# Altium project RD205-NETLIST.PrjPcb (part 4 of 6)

## Sheet 5.SchDoc
size 420 x 297 mm
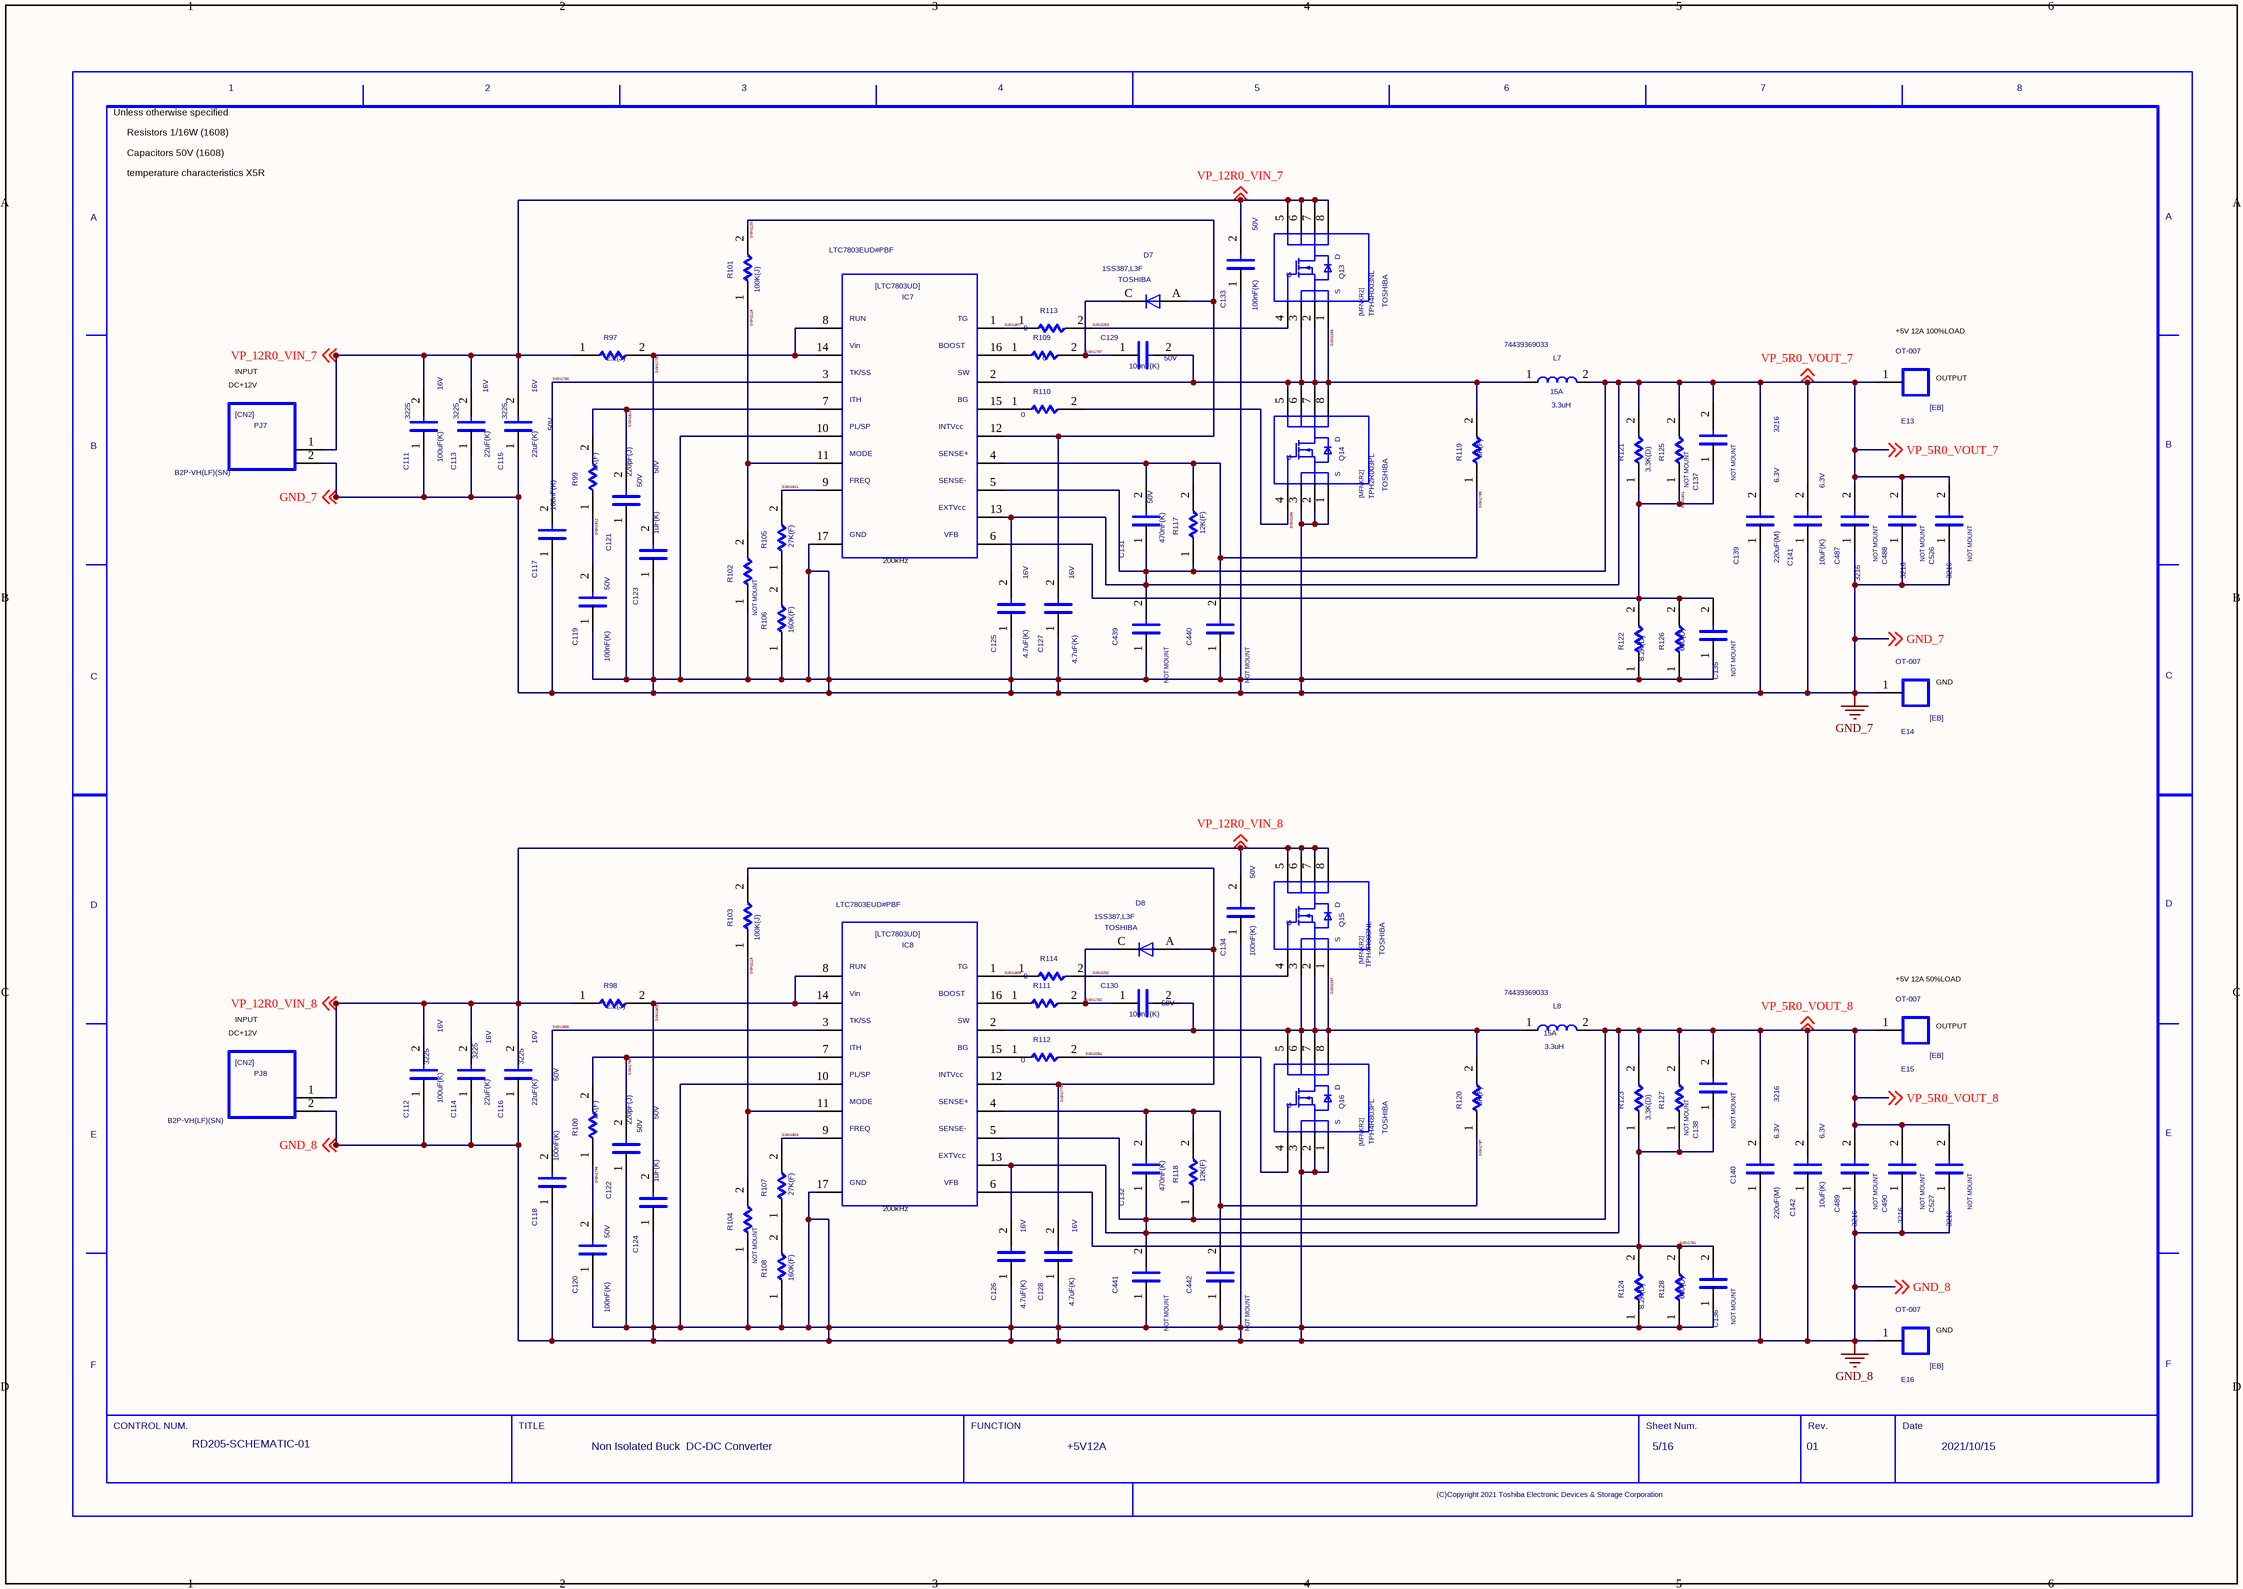
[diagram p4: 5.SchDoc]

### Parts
(Parts that share a designator on the sheet are numbered #1, #2 ... from top to bottom, then left to right.)
C111  SIZECODESMD: 3225  VAL2: 16V  VAL1: 100uF(K)  (hidden comment: C)
C112  SIZECODESMD: 3225  VAL2: 16V  VAL1: 100uF(K)  (hidden comment: C)
C113  SIZECODESMD: 3225  VAL2: 16V  VAL1: 22uF(K)  (hidden comment: C)
C114  SIZECODESMD: 3225  VAL2: 16V  VAL1: 22uF(K)  (hidden comment: C)
C115  SIZECODESMD: 3225  VAL2: 16V  VAL1: 22uF(K)  (hidden comment: C)
C116  SIZECODESMD: 3225  VAL2: 16V  VAL1: 22uF(K)  (hidden comment: C)
C117  VAL2: 50V  VAL1: 100nF(K)  (hidden comment: C)
C118  VAL2: 50V  VAL1: 100nF(K)  (hidden comment: C)
C119  VAL2: 50V  VAL1: 100nF(K)  (hidden comment: C)
C120  VAL2: 50V  VAL1: 100nF(K)  (hidden comment: C)
C121  VAL2: 50V  VAL1: 220pF(J)  (hidden comment: C)
C122  VAL2: 50V  VAL1: 220pF(J)  (hidden comment: C)
C123  VAL2: 50V  VAL1: 1uF(K)  (hidden comment: C)
C124  VAL2: 50V  VAL1: 1uF(K)  (hidden comment: C)
C125  VAL2: 16V  VAL1: 4.7uF(K)  (hidden comment: C)
C126  VAL2: 16V  VAL1: 4.7uF(K)  (hidden comment: C)
C127  VAL2: 16V  VAL1: 4.7uF(K)  (hidden comment: C)
C128  VAL2: 16V  VAL1: 4.7uF(K)  (hidden comment: C)
C129  VAL2: 50V  VAL1: 100nF(K)  (hidden comment: C)
C130  VAL2: 50V  VAL1: 100nF(K)  (hidden comment: C)
C131  VAL2: 50V  VAL1: 470nF(K)  (hidden comment: C)
C132  VAL1: 470nF(K)  (hidden comment: C)
C133  VAL2: 50V  VAL1: 100nF(K)  (hidden comment: C)
C134  VAL2: 50V  VAL1: 100nF(K)  (hidden comment: C)
C135  NOTMOUNT: NOT MOUNT  (hidden comment: C)
C136  NOTMOUNT: NOT MOUNT  (hidden comment: C)
C137  NOTMOUNT: NOT MOUNT  (hidden comment: C)
C138  NOTMOUNT: NOT MOUNT  (hidden comment: C)
C139  SIZECODESMD: 3216  VAL2: 6.3V  VAL1: 220uF(M)  (hidden comment: C)
C140  SIZECODESMD: 3216  VAL2: 6.3V  VAL1: 220uF(M)  (hidden comment: C)
C141  VAL2: 6.3V  VAL1: 10uF(K)  (hidden comment: C)
C142  VAL2: 6.3V  VAL1: 10uF(K)  (hidden comment: C)
C439  NOTMOUNT: NOT MOUNT  (hidden comment: C)
C440  NOTMOUNT: NOT MOUNT  (hidden comment: C)
C441  NOTMOUNT: NOT MOUNT  (hidden comment: C)
C442  NOTMOUNT: NOT MOUNT  (hidden comment: C)
C487  NOTMOUNT: NOT MOUNT  SIZECODESMD: 3216  (hidden comment: C)
C488  NOTMOUNT: NOT MOUNT  SIZECODESMD: 3216  (hidden comment: C)
C489  NOTMOUNT: NOT MOUNT  SIZECODESMD: 3216  (hidden comment: C)
C490  NOTMOUNT: NOT MOUNT  SIZECODESMD: 3216  (hidden comment: C)
C526  NOTMOUNT: NOT MOUNT  SIZECODESMD: 3216  (hidden comment: C)
C527  NOTMOUNT: NOT MOUNT  SIZECODESMD: 3216  (hidden comment: C)
D7  USERCOMPTEXT3: TOSHIBA  VAL3: 1SS387,L3F  (hidden comment: D)
D8  USERCOMPTEXT3: TOSHIBA  VAL3: 1SS387,L3F  (hidden comment: D)
E13  VAL3: OT-007  (hidden comment: EB)
E14  VAL3: OT-007  (hidden comment: EB)
E15  VAL3: OT-007  (hidden comment: EB)
E16  VAL3: OT-007  (hidden comment: EB)
IC7  VAL3: LTC7803EUD#PBF  (hidden comment: LTC7803UD)
IC8  VAL3: LTC7803EUD#PBF  (hidden comment: LTC7803UD)
L7  VAL3: 74439369033  VAL2: 15A  VAL1: 3.3uH  (hidden comment: L)
L8  VAL3: 74439369033  VAL2: 15A  VAL1: 3.3uH  (hidden comment: L)
PJ7  VAL3: B2P-VH(LF)(SN)  (hidden comment: CN2)
PJ8  VAL3: B2P-VH(LF)(SN)  (hidden comment: CN2)
Q13  USERCOMPTEXT3: TOSHIBA  VAL3: TPH4R003NL  (hidden comment: MFNKR2)
Q14  USERCOMPTEXT3: TOSHIBA  VAL3: TPH2R003PL  (hidden comment: MFNKR2)
Q15  USERCOMPTEXT3: TOSHIBA  VAL3: TPH4R003NL  (hidden comment: MFNKR2)
Q16  USERCOMPTEXT3: TOSHIBA  VAL3: TPH4R803PL  (hidden comment: MFNKR2)
R97  VAL1: 2.2(J)  (hidden comment: R)
R98  VAL1: 2.2(J)  (hidden comment: R)
R99  VAL1: 2K(F)  (hidden comment: R)
R100  VAL1: 2K(F)  (hidden comment: R)
R101  VAL1: 100K(J)  (hidden comment: R)
R102  NOTMOUNT: NOT MOUNT  (hidden comment: R)
R103  VAL1: 100K(J)  (hidden comment: R)
R104  NOTMOUNT: NOT MOUNT  (hidden comment: R)
R105  VAL1: 27K(F)  (hidden comment: R)
R106  VAL1: 160K(F)  (hidden comment: R)
R107  VAL1: 27K(F)  (hidden comment: R)
R108  VAL1: 160K(F)  (hidden comment: R)
R109  VAL1: 0  (hidden comment: R)
R110  VAL1: 0  (hidden comment: R)
R111  VAL1: 0  (hidden comment: R)
R112  VAL1: 0  (hidden comment: R)
R113  VAL1: 0  (hidden comment: R)
R114  VAL1: 0  (hidden comment: R)
R117  VAL1: 12K(F)  (hidden comment: R)
R118  VAL1: 12K(F)  (hidden comment: R)
R119  VAL1: 3K(F)  (hidden comment: R)
R120  VAL1: 3K(F)  (hidden comment: R)
R121  VAL1: 3.3K(D)  (hidden comment: R)
R122  VAL1: 8.2K(D)  (hidden comment: R)
R123  VAL1: 3.3K(D)  (hidden comment: R)
R124  VAL1: 8.2K(D)  (hidden comment: R)
R125  NOTMOUNT: NOT MOUNT  (hidden comment: R)
R126  VAL1: 680(D)  (hidden comment: R)
R127  NOTMOUNT: NOT MOUNT  (hidden comment: R)
R128  VAL1: 680(D)  (hidden comment: R)
U?#5  DATE: 2021/10/15  SHEETNUMBER: 5/16  TITLE: Non Isolated Buck / DC-DC Converter  REVISION: 01  DRAWINGNUMBER: RD205-SCHEMATIC-01  FUNCTION: +5V12A  (hidden comment: WAKU_DEF100)

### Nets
GND_7: C111.1 C113.1 C115.1 C117.1 C119.1 C121.1 C123.1 C125.1 C127.1 C133.1 C135.1 C139.1 C141.1 C439.1 C440.1 C487.1 C488.1 C526.1 E14.1 IC7.10 IC7.17 PJ7.2 Q14.1 Q14.2 Q14.3 R102.1 R106.1 R122.1 R126.1 ; off-sheet GND_7
GND_8: C112.1 C114.1 C116.1 C118.1 C120.1 C122.1 C124.1 C126.1 C128.1 C134.1 C136.1 C140.1 C142.1 C441.1 C442.1 C489.1 C490.1 C527.1 E16.1 IC8.10 IC8.17 PJ8.2 Q16.1 Q16.2 Q16.3 R104.1 R108.1 R124.1 R128.1 ; off-sheet GND_8
SIGN1775: C128.2 D8.A IC8.12 R103.2
SIGN1778: C123.2 IC7.8 IC7.14 R97.2
SIGN1780: C122.2 IC8.7 R100.2
SIGN1781: C136.2 C138.1 IC8.6 R123.1 R124.2 R127.1 R128.2
SIGN1782: C130.1 D8.C R111.2
SIGN1786: C117.2 IC7.3
SIGN1787: C132.2 C442.2 IC8.4 R118.2 R120.1
SIGN1789: C131.2 C440.2 IC7.4 R117.2 R119.1
SIGN1796: C120.2 R100.1
SIGN1797: C129.1 D7.C R109.2
SIGN1801: C135.2 C137.1 IC7.6 R121.1 R122.2 R125.1 R126.2
SIGN1803: IC8.9 R107.2
SIGN1805: C124.2 IC8.8 IC8.14 R98.2
SIGN1806: C118.2 IC8.3
SIGN1807: IC7.1 R113.1
SIGN1809: IC8.1 R114.1
SIGN1811: IC7.9 R105.2
SIGN1812: C119.2 R99.1
SIGN1813: C121.2 IC7.7 R99.2
SIGN2118: IC7.11 R101.1 R102.2
SIGN2119: IC8.11 R103.1 R104.2
SIGN2130: C127.2 D7.A IC7.12 R101.2
SIGN2252: Q15.4 R114.2
SIGN2253: Q13.4 R113.2
SIGN2254: Q16.4 R112.2
SIGN2255: Q14.4 R110.2
SIGN2256: C129.2 IC7.2 L7.1 Q13.1 Q13.2 Q13.3 Q14.5 Q14.6 Q14.7 Q14.8 R119.2
SIGN2257: C130.2 IC8.2 L8.1 Q15.1 Q15.2 Q15.3 Q16.5 Q16.6 Q16.7 Q16.8 R120.2
VP_5R0_VOUT_7: C125.2 C131.1 C137.2 C139.2 C141.2 C439.2 C487.2 C488.2 C526.2 E13.1 IC7.5 IC7.13 L7.2 R117.1 R121.2 R125.2 ; off-sheet VP_5R0_VOUT_7
VP_5R0_VOUT_8: C126.2 C132.1 C138.2 C140.2 C142.2 C441.2 C489.2 C490.2 C527.2 E15.1 IC8.5 IC8.13 L8.2 R118.1 R123.2 R127.2 ; off-sheet VP_5R0_VOUT_8
VP_12R0_VIN_7: C111.2 C113.2 C115.2 C133.2 PJ7.1 Q13.5 Q13.6 Q13.7 Q13.8 R97.1 ; off-sheet VP_12R0_VIN_7
VP_12R0_VIN_8: C112.2 C114.2 C116.2 C134.2 PJ8.1 Q15.5 Q15.6 Q15.7 Q15.8 R98.1 ; off-sheet VP_12R0_VIN_8
NetIC7_15: IC7.15 R110.1
NetIC7_16: IC7.16 R109.1
NetIC8_15: IC8.15 R112.1
NetIC8_16: IC8.16 R111.1
NetR105_1: R105.1 R106.2
NetR107_1: R107.1 R108.2

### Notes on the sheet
- Unless otherwise specified
- Resistors 1/16W (1608)
- Capacitors 50V (1608)
- temperature characteristics X5R
- DC+12V
- INPUT
- (near E13) +5V 12A 100%LOAD
- (near E13) OUTPUT
- (near IC7) 200kHz
- (near E14) GND
- (near E15) +5V 12A 50%LOAD
- (near E15) OUTPUT
- (near IC8) 200kHz
- (near E16) GND

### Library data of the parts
C111 C112 = C: SQ_PART_MODEL: CON_100n; FNPARTSNAMEG: CHIP CERAMIC CAPACITOR (3225); USEINPARTSLIST: YES; OriginalSymbolOrigin: (2540,7620); MFSOLDERINGPROP: .; TEMPCHARACTERI2: B; MFFORMINGDIVP: KC; OUMECLASSIFICATION: セラミックコンデンサ; MFMOUNTSYMBOLP: 90; CDMASTERCADCELG: DC903A; PCODE: P03276001115; FNCLASSCODEG: P03-03; MAXGCOUNT: 1; RATEDVOLTAGE: 250; COMPONENTNAME: G36030160049; OUMEMAKER: KYC 京セラ; MFPACKAGEMETHOP: S; NOMINALCAPACITA: 100n; OUMEMAKERKATAMEI: CF32W5R104K250AT; CAPACITANCETOLE: K
C113-C116 = C: SQ_PART_MODEL: CON_22u; FNPARTSNAMEG: CHIP CERAMIC CAPACITOR (3225); USEINPARTSLIST: YES; OriginalSymbolOrigin: (2540,7620); MFSOLDERINGPROP: .; TEMPCHARACTERI2: B; MFFORMINGDIVP: KC; OUMECLASSIFICATION: セラミックコンデンサ; MFMOUNTSYMBOLP: 80; CDMASTERCADCELG: DC903A; PCODE: P03043035626; FNCLASSCODEG: P03-03; MAXGCOUNT: 1; RATEDVOLTAGE: 6.3; COMPONENTNAME: G36030119054; OUMEMAKER: TYD 太陽誘電; MFPACKAGEMETHOP: S; NOMINALCAPACITA: 22u; OUMEMAKERKATAMEI: JMK325BJ226KM-T; CAPACITANCETOLE: K
C117-C120 C129 C130 C133 C134 = C: SQ_PART_MODEL: CON_100n; FNPARTSNAMEG: CHIP CERAMIC CAPACITOR (1608); USEINPARTSLIST: YES; OriginalSymbolOrigin: (2540,7620); MFSOLDERINGPROP: .; TEMPCHARACTERI2: B; MFFORMINGDIVP: KC; OUMECLASSIFICATION: セラミックコンデンサ; SIZECODESMD: 1608; MFMOUNTSYMBOLP: 80; CDMASTERCADCELG: C8100E; PCODE: P03B000000E4; FNCLASSCODEG: P03-03; MAXGCOUNT: 1; RATEDVOLTAGE: 16; COMPONENTNAME: GDM030000598; OUMEMAKER: MRT 村田製作所; MFPACKAGEMETHOP: S; NOMINALCAPACITA: 100n; OUMEMAKERKATAMEI: GRM188B11C104KA01C; CAPACITANCETOLE: K
C121 = C: SQ_PART_MODEL: CON_220p; FNPARTSNAMEG: CHIP CERAMIC CAPACITOR (1608); USEINPARTSLIST: YES; OriginalSymbolOrigin: (2540,7620); CDMASTERCADCELG: C8100E; MFSOLDERINGPROP: .; TEMPCHARACTERI2: CH; MFFORMINGDIVP: KC; OUMECLASSIFICATION: セラミックコンデンサ; SIZECODESMD: 1608; MFMOUNTSYMBOLP: 80; PCODE: P03039269127; FNCLASSCODEG: P03-03; MAXGCOUNT: 1; RATEDVOLTAGE: 50; COMPONENTNAME: G36030011488; OUMEMAKER: KYC 京セラ; MFPACKAGEMETHOP: S; NOMINALCAPACITA: 220p; OUMEMAKERKATAMEI: CM105CH221J50AT; CAPACITANCETOLE: J
C122 = C: SQ_PART_MODEL: CON_220p; FNPARTSNAMEG: CHIP CERAMIC CAPACITOR (1608); USEINPARTSLIST: YES; OriginalSymbolOrigin: (2540,7620); MFSOLDERINGPROP: .; TEMPCHARACTERI2: CH; MFFORMINGDIVP: KC; OUMECLASSIFICATION: セラミックコンデンサ; SIZECODESMD: 1608; MFMOUNTSYMBOLP: 80; CDMASTERCADCELG: C8100E; PCODE: P03039269127; FNCLASSCODEG: P03-03; MAXGCOUNT: 1; RATEDVOLTAGE: 50; COMPONENTNAME: G36030011488; OUMEMAKER: KYC 京セラ; MFPACKAGEMETHOP: S; NOMINALCAPACITA: 220p; OUMEMAKERKATAMEI: CM105CH221J50AT; CAPACITANCETOLE: J
C123 C124 = C: SQ_PART_MODEL: CON_1u; FNPARTSNAMEG: CHIP CERAMIC CAPACITOR (1608); USEINPARTSLIST: YES; OriginalSymbolOrigin: (2540,7620); MFSOLDERINGPROP: .; TEMPCHARACTERI2: B; MFFORMINGDIVP: KC; OUMECLASSIFICATION: セラミックコンデンサ; SIZECODESMD: 1608; MFMOUNTSYMBOLP: 80; CDMASTERCADCELG: C8100E; PCODE: P03039ACE122; FNCLASSCODEG: P03-03; MAXGCOUNT: 1; RATEDVOLTAGE: 6.3; COMPONENTNAME: G36030104159; OUMEMAKER: KYC 京セラ; MFPACKAGEMETHOP: S; NOMINALCAPACITA: 1u; OUMEMAKERKATAMEI: CM105B105K06ATN; CAPACITANCETOLE: K
C125 C126 = C: SQ_PART_MODEL: CON_4.7u; FNPARTSNAMEG: CHIP CERAMIC CAPACITOR (1608); USEINPARTSLIST: YES; OriginalSymbolOrigin: (2540,7620); PCODE: P03B000000MS; MFSOLDERINGPROP: .; TEMPCHARACTERI2: B; MFFORMINGDIVP: KC; OUMECLASSIFICATION: セラミックコンデンサ; SIZECODESMD: 1608; MFMOUNTSYMBOLP: 80; CDMASTERCADCELG: C8100E; FNCLASSCODEG: P03-03; MAXGCOUNT: 1; RATEDVOLTAGE: 4; COMPONENTNAME: GDM030000053; OUMEMAKER: KYC 京セラ; MFPACKAGEMETHOP: S; NOMINALCAPACITA: 4.7u; OUMEMAKERKATAMEI: CM105B475M04AT; CAPACITANCETOLE: M
C127 C128 = C: SQ_PART_MODEL: CON_4.7u; FNPARTSNAMEG: CHIP CERAMIC CAPACITOR (1608); USEINPARTSLIST: YES; OriginalSymbolOrigin: (2540,7620); MFSOLDERINGPROP: .; TEMPCHARACTERI2: B; MFFORMINGDIVP: KC; OUMECLASSIFICATION: セラミックコンデンサ; SIZECODESMD: 1608; MFMOUNTSYMBOLP: 80; CDMASTERCADCELG: C8100E; PCODE: P03B000000MS; FNCLASSCODEG: P03-03; MAXGCOUNT: 1; RATEDVOLTAGE: 4; COMPONENTNAME: GDM030000053; OUMEMAKER: KYC 京セラ; MFPACKAGEMETHOP: S; NOMINALCAPACITA: 4.7u; OUMEMAKERKATAMEI: CM105B475M04AT; CAPACITANCETOLE: M
C131 = C: SQ_PART_MODEL: CON_470n; FNPARTSNAMEG: CHIP CERAMIC CAPACITOR (1608); USEINPARTSLIST: YES; OriginalSymbolOrigin: (2540,7620); MFSOLDERINGPROP: .; TEMPCHARACTERI2: B; MFFORMINGDIVP: KC; OUMECLASSIFICATION: セラミックコンデンサ; SIZECODESMD: 1608; MFMOUNTSYMBOLP: 80; CDMASTERCADCELG: C8100E; PCODE: P03039ABG127; FNCLASSCODEG: P03-03; MAXGCOUNT: 1; RATEDVOLTAGE: 10; COMPONENTNAME: GDM030001129; OUMEMAKER: KYC 京セラ; MFPACKAGEMETHOP: S; NOMINALCAPACITA: 470n; OUMEMAKERKATAMEI: CM105B474K10AT; CAPACITANCETOLE: K
C132 = C: SQ_PART_MODEL: CON_470n; FNPARTSNAMEG: CHIP CERAMIC CAPACITOR (1608); USEINPARTSLIST: YES; OriginalSymbolOrigin: (2540,7620); MFSOLDERINGPROP: .; TEMPCHARACTERI2: B; MFFORMINGDIVP: KC; OUMECLASSIFICATION: セラミックコンデンサ; SIZECODESMD: 1608; MFMOUNTSYMBOLP: 80; CDMASTERCADCELG: C8100E; PCODE: P03039ABG127; FNCLASSCODEG: P03-03; MAXGCOUNT: 1; RATEDVOLTAGE: 10; COMPONENTNAME: GDM030001129; OUMEMAKER: KYC 京セラ; MFPACKAGEMETHOP: S; NOMINALCAPACITA: 470n; OUMEMAKERKATAMEI: CM105B474K10AT; VAL2: 50V; CAPACITANCETOLE: K
C135-C138 = C: SQ_PART_MODEL: CON_100p; FNPARTSNAMEG: CHIP CERAMIC CAPACITOR (1608); USEINPARTSLIST: YES; OriginalSymbolOrigin: (2540,7620); TOLERANCE: J; ASIMVALUE: 100P; MFSOLDERINGPROP: .; TEMPCHARACTERI2: CH; MFFORMINGDIVP: KC; OUMECLASSIFICATION: セラミックコンデンサ; SIZECODESMD: 1608; MFMOUNTSYMBOLP: 80; CDMASTERCADCELG: C8100E; PCODE: P03039177125; FNCLASSCODEG: P03-03; MAXGCOUNT: 1; RATEDVOLTAGE: 50; COMPONENTNAME: G36030011365; OUMEMAKER: KYC 京セラ; MFPACKAGEMETHOP: S; OUMEMAKERKATAMEI: CM105CH101J50AT; VAL2: 50V; VAL1: 100pF(J)
C139 C140 = C: SQ_PART_MODEL: CON_22u; FNPARTSNAMEG: CHIP CERAMIC CAPACITOR (3216); USEINPARTSLIST: YES; OriginalSymbolOrigin: (2540,7620); MFSOLDERINGPROP: .; TEMPCHARACTERI2: B; MFFORMINGDIVP: KC; OUMECLASSIFICATION: セラミックコンデンサ; MFMOUNTSYMBOLP: 80; CDMASTERCADCELG: DC901A; PCODE: P03B0000004V; FNCLASSCODEG: P03-03; MAXGCOUNT: 1; RATEDVOLTAGE: 6.3; COMPONENTNAME: GDM030000020; OUMEMAKER: KYC 京セラ; MFPACKAGEMETHOP: S; NOMINALCAPACITA: 22u; OUMEMAKERKATAMEI: CM316B226M06AT; CAPACITANCETOLE: M
C141 C142 = C: SQ_PART_MODEL: CON_1u; FNPARTSNAMEG: CHIP CERAMIC CAPACITOR (1608); PARTCOMMENT: 代表セル<KC0008> がフットプリントに登録されていません。; USEINPARTSLIST: YES; OriginalSymbolOrigin: (2540,7620); MFSOLDERINGPROP: .; TEMPCHARACTERI2: B; MFFORMINGDIVP: KC; OUMECLASSIFICATION: セラミックコンデンサ; SIZECODESMD: 1608; MFMOUNTSYMBOLP: 80; CDMASTERCADCELG: KC0008; PCODE: P03B000000ZQ; FNCLASSCODEG: P03-03; MAXGCOUNT: 1; RATEDVOLTAGE: 6.3; COMPONENTNAME: GDM030000202; OUMEMAKER: MRT 村田製作所; MFPACKAGEMETHOP: S; NOMINALCAPACITA: 1u; OUMEMAKERKATAMEI: GRM185B10J105KE21D; CAPACITANCETOLE: K
C439-C442 = C: SQ_PART_MODEL: CON_220n; FNPARTSNAMEG: CHIP CERAMIC CAPACITOR (1608); PARTCOMMENT: 代表セル<KC0008> がフットプリントに登録されていません。; USEINPARTSLIST: YES; OriginalSymbolOrigin: (2540,7620); MFSOLDERINGPROP: .; TEMPCHARACTERI2: B; MFFORMINGDIVP: KC; OUMECLASSIFICATION: セラミックコンデンサ; SIZECODESMD: 1608; MFMOUNTSYMBOLP: 80; CDMASTERCADCELG: KC0008; PCODE: P03B000001L3; FNCLASSCODEG: P03-03; MAXGCOUNT: 1; RATEDVOLTAGE: 16; COMPONENTNAME: GDM030001129; OUMEMAKER: MRT 村田製作所; MFPACKAGEMETHOP: S; NOMINALCAPACITA: 220n; OUMEMAKERKATAMEI: GRM188B11C224KA01D; VAL2: 16V; VAL1: 220nF(K); CAPACITANCETOLE: K
C487-C490 C526 C527 = C: SQ_PART_MODEL: CON_22u; FNPARTSNAMEG: CHIP CERAMIC CAPACITOR (3216); USEINPARTSLIST: YES; OriginalSymbolOrigin: (2540,7620); MFSOLDERINGPROP: .; TEMPCHARACTERI2: B; MFFORMINGDIVP: KC; OUMECLASSIFICATION: セラミックコンデンサ; MFMOUNTSYMBOLP: 80; CDMASTERCADCELG: DC901A; PCODE: P03B0000004V; FNCLASSCODEG: P03-03; MAXGCOUNT: 1; RATEDVOLTAGE: 6.3; COMPONENTNAME: GDM030000020; OUMEMAKER: KYC 京セラ; MFPACKAGEMETHOP: S; NOMINALCAPACITA: 22u; OUMEMAKERKATAMEI: CM316B226M06AT; VAL2: 6.3V; VAL1: 22uF(M); CAPACITANCETOLE: M
D7 D8 = D: FNPARTSNAMEG: DIODE; USEINPARTSLIST: YES; PARTNAME: GDM420000143; SAVEAREA0: -565,-171,12979,8058; SAVECOUNT: 1; TIME: 14:49:55; UPDATEUSER: 19870035; UPDATETIME: 14:20:16; OriginalSymbolOrigin: (5080,5080); FORWARDVOLTAGEM: 0; MAXREVERSEVOLTA: 80; COMPONENTNAME: GDM420000143_package; MFSOLDERINGPROP: .; OUMEMAKER: TSB 東芝（ＹＰＳＳ）; QUADMODEL: dummymodel; MFPACKAGEMETHOP: S; MFFORMINGDIVP: MM; MOUNTINGFORMSMD: SMD; OUMECLASSIFICATION: 小信号ダイオード; OUMEMAKERKATAMEI: 1SS387(TPH3,F); CDMASTERCADCELG: D8101D; PCODE: P42B0000008E; FNCLASSCODEG: P42-01
E13-E16 = EB: FNPARTSNAMEG: TERMINAL; USEINPARTSLIST: YES; PARTNAME: 5P9L1232P001; OUMEPARTTYPE: TB; OriginalSymbolOrigin: (2540,12700); COMPONENTNAME: 5P9L1232P001_package; MAXGCOUNT: 1; MFSOLDERINGPROP: .; OUMEMAKER: オサダ; QUADMODEL: dummymodel; MFPACKAGEMETHOP: I; MFFORMINGDIVP: OD; OUMECLASSIFICATION: 端子台、端子板; CDMASTERCADCELG: DE0009; KIND: PBS; PCODE: P29045001117; TERMINALSTYLE: SC; FNCLASSCODEG: P29-01
IC7 IC8 = LTC7803UD: USEINPARTSLIST: YES; SAVECOUNT: 29; SAVEAREA0: -53177,0,89020,58420; TIME: 16:14:14; UPDATEUSER: q91866sr; UPDATETIME: 13:15:36; OriginalSymbolOrigin: (5080,55880); MAXGCOUNT: 1; COMPONENTNAME: LTC7803UD_LTC7803UD; OUMEMAKER: ANALOG DEVICES
L7 L8 = L: USEINPARTSLIST: YES; OriginalSymbolOrigin: (2540,5080); MAXGCOUNT: 1; COMPONENTNAME: L_L; OUMEMAKER: WURTH
PJ7 PJ8 = CN2: FNPARTSNAMEG: 3.96PITCH NYLON CONNECTOR; USEINPARTSLIST: YES; PARTNAME: G36220114012; OUMEPARTTYPE: CN; OriginalSymbolOrigin: (2540,15240); MAXGCOUNT: 1; RATEDCURRENT: 7; COMPONENTNAME: G36220114012_package; MFSOLDERINGPROP: .; OUMEMAKER: JST 日本圧着端子製造; NUMBEROFCONTACT: 2; QUADMODEL: dummymodel; MFPACKAGEMETHOP: I; MFFORMINGDIVP: CU; CONTACTPITCH: 3.96m; OUMEMAKERKATAMEI: B2P-VH; CDMASTERCADCELG: DPJ514; PCODE: P22346001114; TERMINALSTYLE: PW; FNCLASSCODEG: P22-10
Q13-Q16 = MFNKR2: USEINPARTSLIST: YES; PARTNAME: TPH6R003NL; SAVEAREA0: -9199,-39,32138,22820; TIME: 18:57:44; UPDATEUSER: q91866sr; UPDATETIME: 12:36:02; SAVECOUNT: 10; OriginalSymbolOrigin: (5080,20320); MAXGCOUNT: 1; COMPONENTNAME: MFNKR2_MFNKR2
R97 R98 = R: SQ_PART_MODEL: RES_2.2; FNPARTSNAMEG: CHIP RESISTOR (1608); USEINPARTSLIST: YES; OriginalSymbolOrigin: (5080,5080); TOLERANCE: J; ASIMVALUE: 2.2; MAXGCOUNT: 1; COMPONENTNAME: G36010011507; MFSOLDERINGPROP: .; OUMEMAKER: NAE 松下電子部品; MFPACKAGEMETHOP: S; MFFORMINGDIVP: KC; MOUNTINGFORMSMD: SMD; OUMECLASSIFICATION: 表面実装用固定抵抗器; MFMOUNTSYMBOLP: 80; POWERRATING: 63m; OUMEMAKERKATAMEI: ERJ3GEYJ2R2V; NUMBEROFELEMENT: 0; VAL2: 62.5mW; CDMASTERCADCELG: DR802R; PCODE: P01042157622; FNCLASSCODEG: P01-08
R99 R100 = R: SQ_PART_MODEL: RES_2K; FNPARTSNAMEG: CHIP RESISTOR (1608); USEINPARTSLIST: YES; OriginalSymbolOrigin: (5080,5080); MAXGCOUNT: 1; COMPONENTNAME: G36010027A10; MFSOLDERINGPROP: .; OUMEMAKER: KAM 釜屋電機; MFPACKAGEMETHOP: S; MFFORMINGDIVP: KC; MOUNTINGFORMSMD: SMD; OUMECLASSIFICATION: 表面実装用固定抵抗器; RESISTANCETOLER: F; MFMOUNTSYMBOLP: 80; POWERRATING: 63m; OUMEMAKERKATAMEI: RMC1/16-202FTP; NOMINALRESISTAN: 2K; NUMBEROFELEMENT: 0; VAL2: 62.5mW; CDMASTERCADCELG: DR802R; PCODE: P01042243325; FNCLASSCODEG: P01-08
R101 R103 = R: SQ_PART_MODEL: RES_100K; FNPARTSNAMEG: CHIP RESISTOR (1608); USEINPARTSLIST: YES; OriginalSymbolOrigin: (5080,5080); TOLERANCE: J; ASIMVALUE: 100K; MFSOLDERINGPROP: .; MFPACKAGEMETHOP: S; MFFORMINGDIVP: KC; MOUNTINGFORMSMD: SMD; MFMOUNTSYMBOLP: 80; NUMBEROFELEMENT: 0; PCODE: P01042047220; MAXGCOUNT: 1; COMPONENTNAME: G36010011057; OUMEMAKER: HDK 北陸電気工業; OUMECLASSIFICATION: 表面実装用固定抵抗器; POWERRATING: 63m; OUMEMAKERKATAMEI: CR1/16 104JV; VAL2: 62.5mW; CDMASTERCADCELG: DR802R; FNCLASSCODEG: P01-08
R102 R104 = R: SQ_PART_MODEL: RES_10; FNPARTSNAMEG: CHIP RESISTOR (1608); USEINPARTSLIST: YES; OriginalSymbolOrigin: (5080,5080); TOLERANCE: F; ASIMVALUE: 10; MFSOLDERINGPROP: .; MFPACKAGEMETHOP: S; MFFORMINGDIVP: KC; MOUNTINGFORMSMD: SMD; MFMOUNTSYMBOLP: 80; NUMBEROFELEMENT: 0; PCODE: P01042036620; MAXGCOUNT: 1; COMPONENTNAME: G36010104063; OUMEMAKER: NAE 松下電子部品; OUMECLASSIFICATION: 表面実装用固定抵抗器; POWERRATING: 63m; OUMEMAKERKATAMEI: ERJ3GEYF100V; VAL2: 62.5mW; VAL1: 10(F); CDMASTERCADCELG: DR802R; FNCLASSCODEG: P01-08
R105 R107 = R: SQ_PART_MODEL: RES_27K; FNPARTSNAMEG: CHIP RESISTOR (1608); USEINPARTSLIST: YES; OriginalSymbolOrigin: (5080,5080); MAXGCOUNT: 1; TOLERANCE: F; COMPONENTNAME: G36010027195; MFSOLDERINGPROP: .; OUMEMAKER: NAE 松下電子部品; MFPACKAGEMETHOP: S; MFFORMINGDIVP: KC; MOUNTINGFORMSMD: SMD; OUMECLASSIFICATION: 表面実装用固定抵抗器; ASIMVALUE: 27K; MFMOUNTSYMBOLP: 80; POWERRATING: 63m; OUMEMAKERKATAMEI: ERJ3GEYF273V; NUMBEROFELEMENT: 0; VAL2: 62.5mW; CDMASTERCADCELG: DR802R; PCODE: P01042508622; FNCLASSCODEG: P01-08
R106 R108 = R: SQ_PART_MODEL: RES_160K; FNPARTSNAMEG: CHIP RESISTOR (1608); USEINPARTSLIST: YES; OriginalSymbolOrigin: (5080,5080); MAXGCOUNT: 1; COMPONENTNAME: G51011061108; MFSOLDERINGPROP: .; OUMEMAKER: HDK 北陸電気工業; MFPACKAGEMETHOP: S; MFFORMINGDIVP: KC; MOUNTINGFORMSMD: SMD; OUMECLASSIFICATION: 表面実装用固定抵抗器; RESISTANCETOLER: F; MFMOUNTSYMBOLP: 80; POWERRATING: 63m; OUMEMAKERKATAMEI: CR1/16 164FV; NOMINALRESISTAN: 160K; NUMBEROFELEMENT: 0; VAL2: 62.5mW; CDMASTERCADCELG: DR802R; PCODE: P01042125225; FNCLASSCODEG: P01-08
R109 R111 = R: SQ_PART_MODEL: RES_10; FNPARTSNAMEG: CHIP RESISTOR (1608); USEINPARTSLIST: YES; OriginalSymbolOrigin: (5080,5080); TOLERANCE: F; ASIMVALUE: 10; MFSOLDERINGPROP: .; MFPACKAGEMETHOP: S; MFFORMINGDIVP: KC; MOUNTINGFORMSMD: SMD; MFMOUNTSYMBOLP: 80; PCODE: P01042036620; MAXGCOUNT: 1; COMPONENTNAME: G36010104063; OUMEMAKER: NAE 松下電子部品; OUMECLASSIFICATION: 表面実装用固定抵抗器; POWERRATING: 63m; OUMEMAKERKATAMEI: ERJ3GEYF100V; VAL2: 62.5mW; CDMASTERCADCELG: DR802R; FNCLASSCODEG: P01-08
R110 R112-R114 = R: SQ_PART_MODEL: RES_10; FNPARTSNAMEG: CHIP RESISTOR (2012); USEINPARTSLIST: YES; OriginalSymbolOrigin: (5080,5080); MAXGCOUNT: 1; TOLERANCE: F; COMPONENTNAME: 5P9L1083P100; MFSOLDERINGPROP: .; OUMEMAKER: 北陸電気工業; MFPACKAGEMETHOP: S; MFFORMINGDIVP: KC; MOUNTINGFORMSMD: SMD; OUMECLASSIFICATION: 表面実装用固定抵抗器; ASIMVALUE: 10; MFMOUNTSYMBOLP: 90; POWERRATING: 100m; OUMEMAKERKATAMEI: CR1/10 100FV Pb(F); VAL2: 125mW; CDMASTERCADCELG: DR910A; PCODE: P01043091222; FNCLASSCODEG: P01-08
R117 R118 = R: SQ_PART_MODEL: RES_12K; FNPARTSNAMEG: CHIP RESISTOR (1608); USEINPARTSLIST: YES; OriginalSymbolOrigin: (5080,5080); TOLERANCE: F; ASIMVALUE: 12K; MAXGCOUNT: 1; COMPONENTNAME: G36010027195; MFSOLDERINGPROP: .; OUMEMAKER: HDK 北陸電気工業; MFPACKAGEMETHOP: S; MFFORMINGDIVP: KC; MOUNTINGFORMSMD: SMD; OUMECLASSIFICATION: 表面実装用固定抵抗器; MFMOUNTSYMBOLP: 80; POWERRATING: 63m; OUMEMAKERKATAMEI: CR1/16 123FV; NUMBEROFELEMENT: 0; VAL2: 62.5mW; CDMASTERCADCELG: DR802R; PCODE: P01042514227; FNCLASSCODEG: P01-08
R119 R120 = R: SQ_PART_MODEL: RES_3K; FNPARTSNAMEG: CHIP RESISTOR (1608); USEINPARTSLIST: YES; OriginalSymbolOrigin: (5080,5080); MAXGCOUNT: 1; COMPONENTNAME: G36010027409; MFSOLDERINGPROP: .; OUMEMAKER: KOA ＫＯＡ; MFPACKAGEMETHOP: S; MFFORMINGDIVP: KC; MOUNTINGFORMSMD: SMD; OUMECLASSIFICATION: 表面実装用固定抵抗器; RESISTANCETOLER: F; MFMOUNTSYMBOLP: 80; POWERRATING: 63m; OUMEMAKERKATAMEI: RK73H1JTD3001F; NOMINALRESISTAN: 3K; NUMBEROFELEMENT: 0; VAL2: 62.5mW; CDMASTERCADCELG: DR802R; PCODE: P01042331428; FNCLASSCODEG: P01-08
R121 R123 = R: SQ_PART_MODEL: RES_3.3K; FNPARTSNAMEG: CHIP RESISTOR (1608); USEINPARTSLIST: YES; OriginalSymbolOrigin: (5080,5080); MAXGCOUNT: 1; COMPONENTNAME: G36010014485; MFSOLDERINGPROP: .; OUMEMAKER: SSM 進工業; MFPACKAGEMETHOP: S; MFFORMINGDIVP: KC; MOUNTINGFORMSMD: SMD; OUMECLASSIFICATION: 表面実装用固定抵抗器; RESISTANCETOLER: D; MFMOUNTSYMBOLP: 80; POWERRATING: 63m; OUMEMAKERKATAMEI: RR0816P-332-D; NOMINALRESISTAN: 3.3K; NUMBEROFELEMENT: 0; VAL2: 62.5mW; CDMASTERCADCELG: DR802R; PCODE: P01042249822; FNCLASSCODEG: P01-08
R122 R124 = R: ICX_PART_MODEL: RES_8.2K; FNPARTSNAMEG: CHIP RESISTOR (1608); OriginalSymbolOrigin: (5080,5080); FNCLASSCODEG: P01-08; PCODE: P01117051114; CDMASTERCADCELG: DR802R; USEWITHSCHEMA: YES; VAL2: 62.5mW; NUMBEROFELEMENT: 0; NOMINALRESISTAN: 8.2K; OUMEMAKERKATAMEI: RK73G1JTD822D; POWERRATING: 63m; MFMOUNTSYMBOLP: 80; RESISTANCETOLER: D; FUNCTION: G36010129479; OUMECLASSIFICATION: 表面実装用固定抵抗器; MOUNTINGFORMSMD: SMD; MFFORMINGDIVP: KC; MFPACKAGEMETHOP: S; OUMEMAKER: KOA ＫＯＡ; MFSOLDERINGPROP: .; MAXGCOUNT: 1
R125 R127 = R: SQ_PART_MODEL: RES_3.3K; FNPARTSNAMEG: CHIP RESISTOR (1608); USEINPARTSLIST: YES; OriginalSymbolOrigin: (5080,5080); TOLERANCE: F; ASIMVALUE: 3.3K; MAXGCOUNT: 1; COMPONENTNAME: G36010027027; MFSOLDERINGPROP: .; OUMEMAKER: ROH ロー・; MFPACKAGEMETHOP: S; MFFORMINGDIVP: KC; MOUNTINGFORMSMD: SMD; OUMECLASSIFICATION: 表面実装用固定抵抗器; MFMOUNTSYMBOLP: 80; POWERRATING: 63m; OUMEMAKERKATAMEI: MCR03EZPFX3301; NUMBEROFELEMENT: 0; VAL2: 62.5mW; VAL1: 3.3K(F); CDMASTERCADCELG: DR802R; PCODE: P01042250729; FNCLASSCODEG: P01-08
R126 R128 = R: ICX_PART_MODEL: RES_680; FNPARTSNAMEG: CHIP RESISTOR (1608); OriginalSymbolOrigin: (5080,5080); FNCLASSCODEG: P01-08; PCODE: P01117025115; CDMASTERCADCELG: DR802R; USEWITHSCHEMA: YES; VAL2: 62.5mW; NUMBEROFELEMENT: 0; NOMINALRESISTAN: 680; OUMEMAKERKATAMEI: RK73G1JTD681D; POWERRATING: 63m; MFMOUNTSYMBOLP: 80; RESISTANCETOLER: D; FUNCTION: G36010129219; OUMECLASSIFICATION: 表面実装用固定抵抗器; MOUNTINGFORMSMD: SMD; MFFORMINGDIVP: KC; MFPACKAGEMETHOP: S; OUMEMAKER: KOA ＫＯＡ; MFSOLDERINGPROP: .; MAXGCOUNT: 1
U?#5 = WAKU_DEF100: PLOTTIME: HH:MM; SAVEAREA0: 330961,54,387907,31546; TIME: 19:23:07; UPDATEUSER: t5459927; UPDATETIME: 15:33:39; SAVECOUNT: 6; OriginalSymbolOrigin: (10160,284480); DESIGNED: ***

## Sheet 6.SchDoc
size 420 x 297 mm
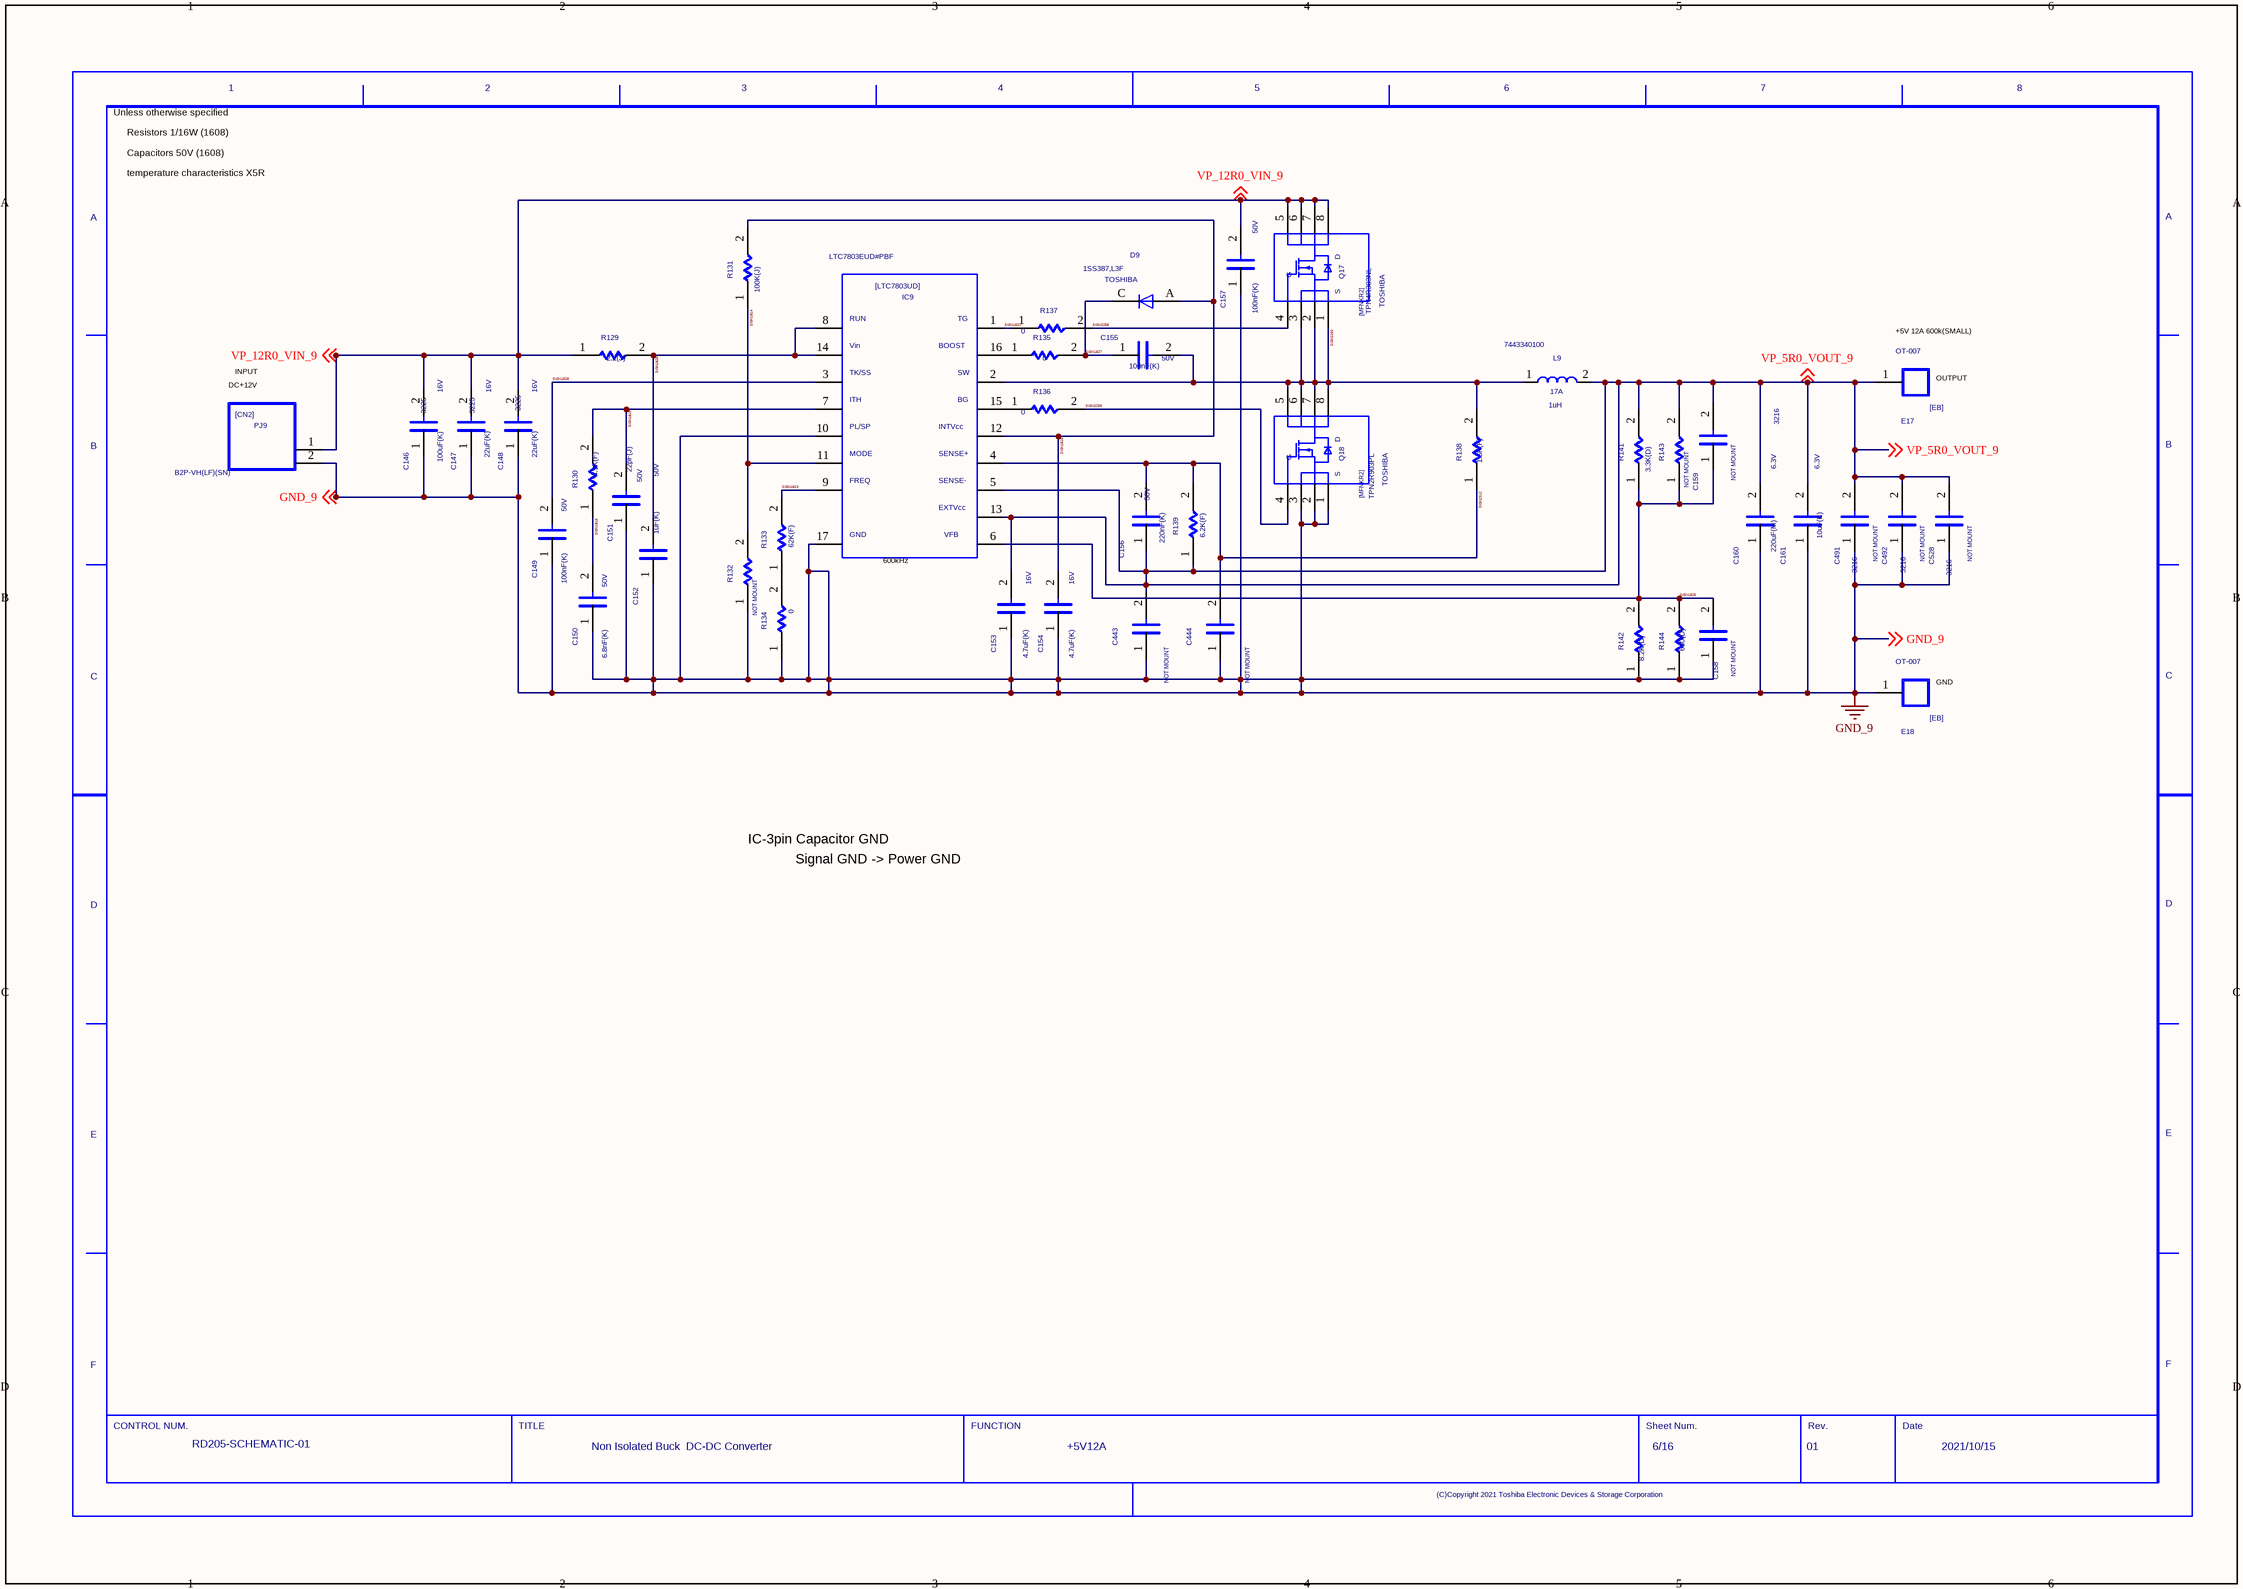
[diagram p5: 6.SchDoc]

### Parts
(Parts that share a designator on the sheet are numbered #1, #2 ... from top to bottom, then left to right.)
C146  SIZECODESMD: 3225  VAL2: 16V  VAL1: 100uF(K)  (hidden comment: C)
C147  SIZECODESMD: 3225  VAL2: 16V  VAL1: 22uF(K)  (hidden comment: C)
C148  SIZECODESMD: 3225  VAL2: 16V  VAL1: 22uF(K)  (hidden comment: C)
C149  VAL2: 50V  VAL1: 100nF(K)  (hidden comment: C)
C150  VAL2: 50V  VAL1: 6.8nF(K)  (hidden comment: C)
C151  VAL2: 50V  VAL1: 22pF(J)  (hidden comment: C)
C152  VAL2: 50V  VAL1: 1uF(K)  (hidden comment: C)
C153  VAL2: 16V  VAL1: 4.7uF(K)  (hidden comment: C)
C154  VAL2: 16V  VAL1: 4.7uF(K)  (hidden comment: C)
C155  VAL2: 50V  VAL1: 100nF(K)  (hidden comment: C)
C156  VAL2: 50V  VAL1: 220nF(K)  (hidden comment: C)
C157  VAL2: 50V  VAL1: 100nF(K)  (hidden comment: C)
C158  NOTMOUNT: NOT MOUNT  (hidden comment: C)
C159  NOTMOUNT: NOT MOUNT  (hidden comment: C)
C160  SIZECODESMD: 3216  VAL2: 6.3V  VAL1: 220uF(M)  (hidden comment: C)
C161  VAL2: 6.3V  VAL1: 10uF(K)  (hidden comment: C)
C443  NOTMOUNT: NOT MOUNT  (hidden comment: C)
C444  NOTMOUNT: NOT MOUNT  (hidden comment: C)
C491  NOTMOUNT: NOT MOUNT  SIZECODESMD: 3216  (hidden comment: C)
C492  NOTMOUNT: NOT MOUNT  SIZECODESMD: 3216  (hidden comment: C)
C528  NOTMOUNT: NOT MOUNT  SIZECODESMD: 3216  (hidden comment: C)
D9  USERCOMPTEXT3: TOSHIBA  VAL3: 1SS387,L3F  (hidden comment: D)
E17  VAL3: OT-007  (hidden comment: EB)
E18  VAL3: OT-007  (hidden comment: EB)
IC9  VAL3: LTC7803EUD#PBF  (hidden comment: LTC7803UD)
L9  VAL3: 7443340100  VAL2: 17A  VAL1: 1uH  (hidden comment: L)
PJ9  VAL3: B2P-VH(LF)(SN)  (hidden comment: CN2)
Q17  USERCOMPTEXT3: TOSHIBA  VAL3: TPN4R303NL  (hidden comment: MFNKR2)
Q18  USERCOMPTEXT3: TOSHIBA  VAL3: TPN2R903PL  (hidden comment: MFNKR2)
R129  VAL1: 2.2(J)  (hidden comment: R)
R130  VAL1: 4.3K(F)  (hidden comment: R)
R131  VAL1: 100K(J)  (hidden comment: R)
R132  NOTMOUNT: NOT MOUNT  (hidden comment: R)
R133  VAL1: 62K(F)  (hidden comment: R)
R134  VAL1: 0  (hidden comment: R)
R135  VAL1: 0  (hidden comment: R)
R136  VAL1: 0  (hidden comment: R)
R137  VAL1: 0  (hidden comment: R)
R138  VAL1: 1.5K(F)  (hidden comment: R)
R139  VAL1: 6.2K(F)  (hidden comment: R)
R141  VAL1: 3.3K(D)  (hidden comment: R)
R142  VAL1: 8.2K(D)  (hidden comment: R)
R143  NOTMOUNT: NOT MOUNT  (hidden comment: R)
R144  VAL1: 680(D)  (hidden comment: R)
U?#6  DATE: 2021/10/15  SHEETNUMBER: 6/16  TITLE: Non Isolated Buck / DC-DC Converter  REVISION: 01  DRAWINGNUMBER: RD205-SCHEMATIC-01  FUNCTION: +5V12A  (hidden comment: WAKU_DEF100)

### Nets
GND_9: C146.1 C147.1 C148.1 C149.1 C150.1 C151.1 C152.1 C153.1 C154.1 C157.1 C158.1 C160.1 C161.1 C443.1 C444.1 C491.1 C492.1 C528.1 E18.1 IC9.10 IC9.17 PJ9.2 Q18.1 Q18.2 Q18.3 R132.1 R134.1 R142.1 R144.1 ; off-sheet GND_9
SIGN1814: IC9.11 R131.1 R132.2
SIGN1815: C154.2 D9.A IC9.12 R131.2
SIGN1816: C150.2 R130.1
SIGN1819: C151.2 IC9.7 R130.2
SIGN1822: IC9.1 R137.1
SIGN1823: IC9.9 R133.2
SIGN1825: C158.2 C159.1 IC9.6 R141.1 R142.2 R143.1 R144.2
SIGN1826: C152.2 IC9.8 IC9.14 R129.2
SIGN1827: C155.1 D9.C R135.2
SIGN1828: C149.2 IC9.3
SIGN2258: Q17.4 R137.2
SIGN2259: Q18.4 R136.2
SIGN2260: C155.2 IC9.2 L9.1 Q17.1 Q17.2 Q17.3 Q18.5 Q18.6 Q18.7 Q18.8 R138.2
SIGN2312: C156.2 C444.2 IC9.4 R138.1 R139.2
VP_5R0_VOUT_9: C153.2 C156.1 C159.2 C160.2 C161.2 C443.2 C491.2 C492.2 C528.2 E17.1 IC9.5 IC9.13 L9.2 R139.1 R141.2 R143.2 ; off-sheet VP_5R0_VOUT_9
VP_12R0_VIN_9: C146.2 C147.2 C148.2 C157.2 PJ9.1 Q17.5 Q17.6 Q17.7 Q17.8 R129.1 ; off-sheet VP_12R0_VIN_9
NetIC9_15: IC9.15 R136.1
NetIC9_16: IC9.16 R135.1
NetR133_1: R133.1 R134.2

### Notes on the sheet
- Unless otherwise specified
- Resistors 1/16W (1608)
- Capacitors 50V (1608)
- temperature characteristics X5R
- DC+12V
- INPUT
- (near E17) +5V 12A 600k(SMALL)
- (near E17) OUTPUT
- (near IC9) 600kHz
- (near E18) GND
- IC-3pin Capacitor GND
- Signal GND -> Power GND

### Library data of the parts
C146 = C: as C111 on sheet 5
C147 C148 = C: as C113 on sheet 5
C149 C155 C157 = C: as C117 on sheet 5
C150 = C: SQ_PART_MODEL: CON_6.8n; FNPARTSNAMEG: CHIP CERAMIC CAPACITOR (1608); USEINPARTSLIST: YES; OriginalSymbolOrigin: (2540,7620); TOLERANCE: K; ASIMVALUE: 6.8N; MFSOLDERINGPROP: .; TEMPCHARACTERI2: B; MFFORMINGDIVP: KC; OUMECLASSIFICATION: セラミックコンデンサ; SIZECODESMD: 1608; MFMOUNTSYMBOLP: 80; CDMASTERCADCELG: C8100E; PCODE: P03039109225; FNCLASSCODEG: P03-03; MAXGCOUNT: 1; RATEDVOLTAGE: 50; COMPONENTNAME: G36030011440; OUMEMAKER: MRT 村田製作所; MFPACKAGEMETHOP: S; OUMEMAKERKATAMEI: GRM39B682K50PT
C151 = C: SQ_PART_MODEL: CON_22p; FNPARTSNAMEG: CHIP CERAMIC CAPACITOR (1608); USEINPARTSLIST: YES; OriginalSymbolOrigin: (2540,7620); TOLERANCE: J; ASIMVALUE: 22P; MFSOLDERINGPROP: .; TEMPCHARACTERI2: CH; MFFORMINGDIVP: KC; OUMECLASSIFICATION: セラミックコンデンサ; SIZECODESMD: 1608; MFMOUNTSYMBOLP: 80; CDMASTERCADCELG: C8100E; PCODE: P03039A02625; FNCLASSCODEG: P03-03; MAXGCOUNT: 1; RATEDVOLTAGE: 50; COMPONENTNAME: G36030011129; OUMEMAKER: TYD 太陽誘電; MFPACKAGEMETHOP: S; OUMEMAKERKATAMEI: UMK107CH220JZ-T
C152 = C: as C123 on sheet 5
C153 = C: as C125 on sheet 5
C154 = C: as C127 on sheet 5
C156 = C: SQ_PART_MODEL: CON_220n; FNPARTSNAMEG: CHIP CERAMIC CAPACITOR (1608); PARTCOMMENT: 代表セル<KC0008> がフットプリントに登録されていません。; USEINPARTSLIST: YES; OriginalSymbolOrigin: (2540,7620); MFSOLDERINGPROP: .; TEMPCHARACTERI2: B; MFFORMINGDIVP: KC; OUMECLASSIFICATION: セラミックコンデンサ; SIZECODESMD: 1608; MFMOUNTSYMBOLP: 80; CDMASTERCADCELG: KC0008; PCODE: P03B000001L3; FNCLASSCODEG: P03-03; MAXGCOUNT: 1; RATEDVOLTAGE: 16; COMPONENTNAME: GDM030001129; OUMEMAKER: MRT 村田製作所; MFPACKAGEMETHOP: S; NOMINALCAPACITA: 220n; OUMEMAKERKATAMEI: GRM188B11C224KA01D; CAPACITANCETOLE: K
C158 C159 = C: as C135 on sheet 5
C160 = C: as C139 on sheet 5
C161 = C: SQ_PART_MODEL: CON_1u; FNPARTSNAMEG: CHIP CERAMIC CAPACITOR (1608); PARTCOMMENT: 代表セル<KC0008> がフットプリントに登録されていません。; USEINPARTSLIST: YES; OriginalSymbolOrigin: (2540,7620); MFSOLDERINGPROP: .; TEMPCHARACTERI2: B; MFPACKAGEMETHOP: S; MFFORMINGDIVP: KC; MFMOUNTSYMBOLP: 80; PCODE: P03B000000ZQ; OUMECLASSIFICATION: セラミックコンデンサ; SIZECODESMD: 1608; CDMASTERCADCELG: KC0008; FNCLASSCODEG: P03-03; MAXGCOUNT: 1; RATEDVOLTAGE: 6.3; COMPONENTNAME: GDM030000202; OUMEMAKER: MRT 村田製作所; NOMINALCAPACITA: 1u; OUMEMAKERKATAMEI: GRM185B10J105KE21D; CAPACITANCETOLE: K
C443 C444 = C: as C439 on sheet 5
C491 C492 C528 = C: as C487 on sheet 5
D9 = D: as D7 on sheet 5
E17 E18 = EB: as E13 on sheet 5
IC9 = LTC7803UD: as IC7 on sheet 5
L9 = L: USEINPARTSLIST: YES; PARTNAME: 7443340068; OriginalSymbolOrigin: (2540,5080); MAXGCOUNT: 1; COMPONENTNAME: L_L; OUMEMAKER: WURTH
PJ9 = CN2: as PJ7 on sheet 5
Q17 Q18 = MFNKR2: USEINPARTSLIST: YES; PARTNAME: TPN1R603PL; SAVEAREA0: -9199,-39,32138,22820; TIME: 18:57:44; UPDATEUSER: q91866sr; UPDATETIME: 12:36:02; SAVECOUNT: 10; OriginalSymbolOrigin: (5080,20320); MAXGCOUNT: 1; COMPONENTNAME: MFNKR2_MFNKR2
R129 = R: as R97 on sheet 5
R130 = R: SQ_PART_MODEL: RES_4.3K; FNPARTSNAMEG: CHIP RESISTOR (1608); USEINPARTSLIST: YES; OriginalSymbolOrigin: (5080,5080); PCODE: P01042335624; MAXGCOUNT: 1; COMPONENTNAME: G5101105L102; MFSOLDERINGPROP: .; OUMEMAKER: NAE 松下電子部品; MFPACKAGEMETHOP: S; MFFORMINGDIVP: KC; MOUNTINGFORMSMD: SMD; OUMECLASSIFICATION: 表面実装用固定抵抗器; RESISTANCETOLER: F; MFMOUNTSYMBOLP: 80; POWERRATING: 63m; OUMEMAKERKATAMEI: ERJ3GEYF432V; NOMINALRESISTAN: 4.3K; NUMBEROFELEMENT: 0; VAL2: 62.5mW; CDMASTERCADCELG: DR802R; FNCLASSCODEG: P01-08
R131 = R: as R101 on sheet 5
R132 = R: as R102 on sheet 5
R133 = R: SQ_PART_MODEL: RES_62K; FNPARTSNAMEG: CHIP RESISTOR (1608); USEINPARTSLIST: YES; OriginalSymbolOrigin: (5080,5080); MAXGCOUNT: 1; TOLERANCE: F; COMPONENTNAME: G36010027355; MFSOLDERINGPROP: .; OUMEMAKER: HDK 北陸電気工業; MFPACKAGEMETHOP: S; MFFORMINGDIVP: KC; MOUNTINGFORMSMD: SMD; OUMECLASSIFICATION: 表面実装用固定抵抗器; ASIMVALUE: 62K; MFMOUNTSYMBOLP: 80; POWERRATING: 63m; OUMEMAKERKATAMEI: CR1/16 623FV; NUMBEROFELEMENT: 0; VAL2: 62.5mW; CDMASTERCADCELG: DR802R; PCODE: P01042441226; FNCLASSCODEG: P01-08
R134 = R: SQ_PART_MODEL: RES_10; FNPARTSNAMEG: CHIP RESISTOR (1608); USEINPARTSLIST: YES; OriginalSymbolOrigin: (5080,5080); TOLERANCE: F; ASIMVALUE: 10; MAXGCOUNT: 1; COMPONENTNAME: G36010104063; MFSOLDERINGPROP: .; OUMEMAKER: NAE 松下電子部品; MFPACKAGEMETHOP: S; MFFORMINGDIVP: KC; MOUNTINGFORMSMD: SMD; OUMECLASSIFICATION: 表面実装用固定抵抗器; MFMOUNTSYMBOLP: 80; POWERRATING: 63m; OUMEMAKERKATAMEI: ERJ3GEYF100V; VAL2: 62.5mW; CDMASTERCADCELG: DR802R; PCODE: P01042036620; FNCLASSCODEG: P01-08
R135 = R: as R109 on sheet 5
R136 R137 = R: as R110 on sheet 5
R138 = R: SQ_PART_MODEL: RES_1.5K; FNPARTSNAMEG: CHIP RESISTOR (1608); USEINPARTSLIST: YES; OriginalSymbolOrigin: (5080,5080); TOLERANCE: F; ASIMVALUE: 1.5K; MAXGCOUNT: 1; COMPONENTNAME: G36010027232; MFSOLDERINGPROP: .; OUMEMAKER: HDK 北陸電気工業; MFPACKAGEMETHOP: S; MFFORMINGDIVP: KC; MOUNTINGFORMSMD: SMD; OUMECLASSIFICATION: 表面実装用固定抵抗器; MFMOUNTSYMBOLP: 80; POWERRATING: 63m; OUMEMAKERKATAMEI: CR1/16 152FV; NUMBEROFELEMENT: 0; VAL2: 62.5mW; CDMASTERCADCELG: DR802R; PCODE: P01042512223; FNCLASSCODEG: P01-08
R139 = R: SQ_PART_MODEL: RES_6.2K; FNPARTSNAMEG: CHIP RESISTOR (1608); USEINPARTSLIST: YES; OriginalSymbolOrigin: (5080,5080); TOLERANCE: F; ASIMVALUE: 6.2K; MAXGCOUNT: 1; COMPONENTNAME: G36010027119; MFSOLDERINGPROP: .; OUMEMAKER: KOA ＫＯＡ; MFPACKAGEMETHOP: S; MFFORMINGDIVP: KC; MOUNTINGFORMSMD: SMD; OUMECLASSIFICATION: 表面実装用固定抵抗器; MFMOUNTSYMBOLP: 80; POWERRATING: 63m; OUMEMAKERKATAMEI: RK73H1JTD6201F; NUMBEROFELEMENT: 0; VAL2: 62.5mW; CDMASTERCADCELG: DR802R; PCODE: P01042419423; FNCLASSCODEG: P01-08
R141 = R: as R121 on sheet 5
R142 = R: as R122 on sheet 5
R143 = R: as R125 on sheet 5
R144 = R: as R126 on sheet 5
U?#6 = WAKU_DEF100: PLOTTIME: HH:MM; SAVEAREA0: 330961,54,387907,31546; TIME: 19:23:07; UPDATEUSER: t5459927; UPDATETIME: 15:33:40; SAVECOUNT: 6; OriginalSymbolOrigin: (10160,284480); DESIGNED: ***

## Sheet 7.SchDoc
size 420 x 297 mm
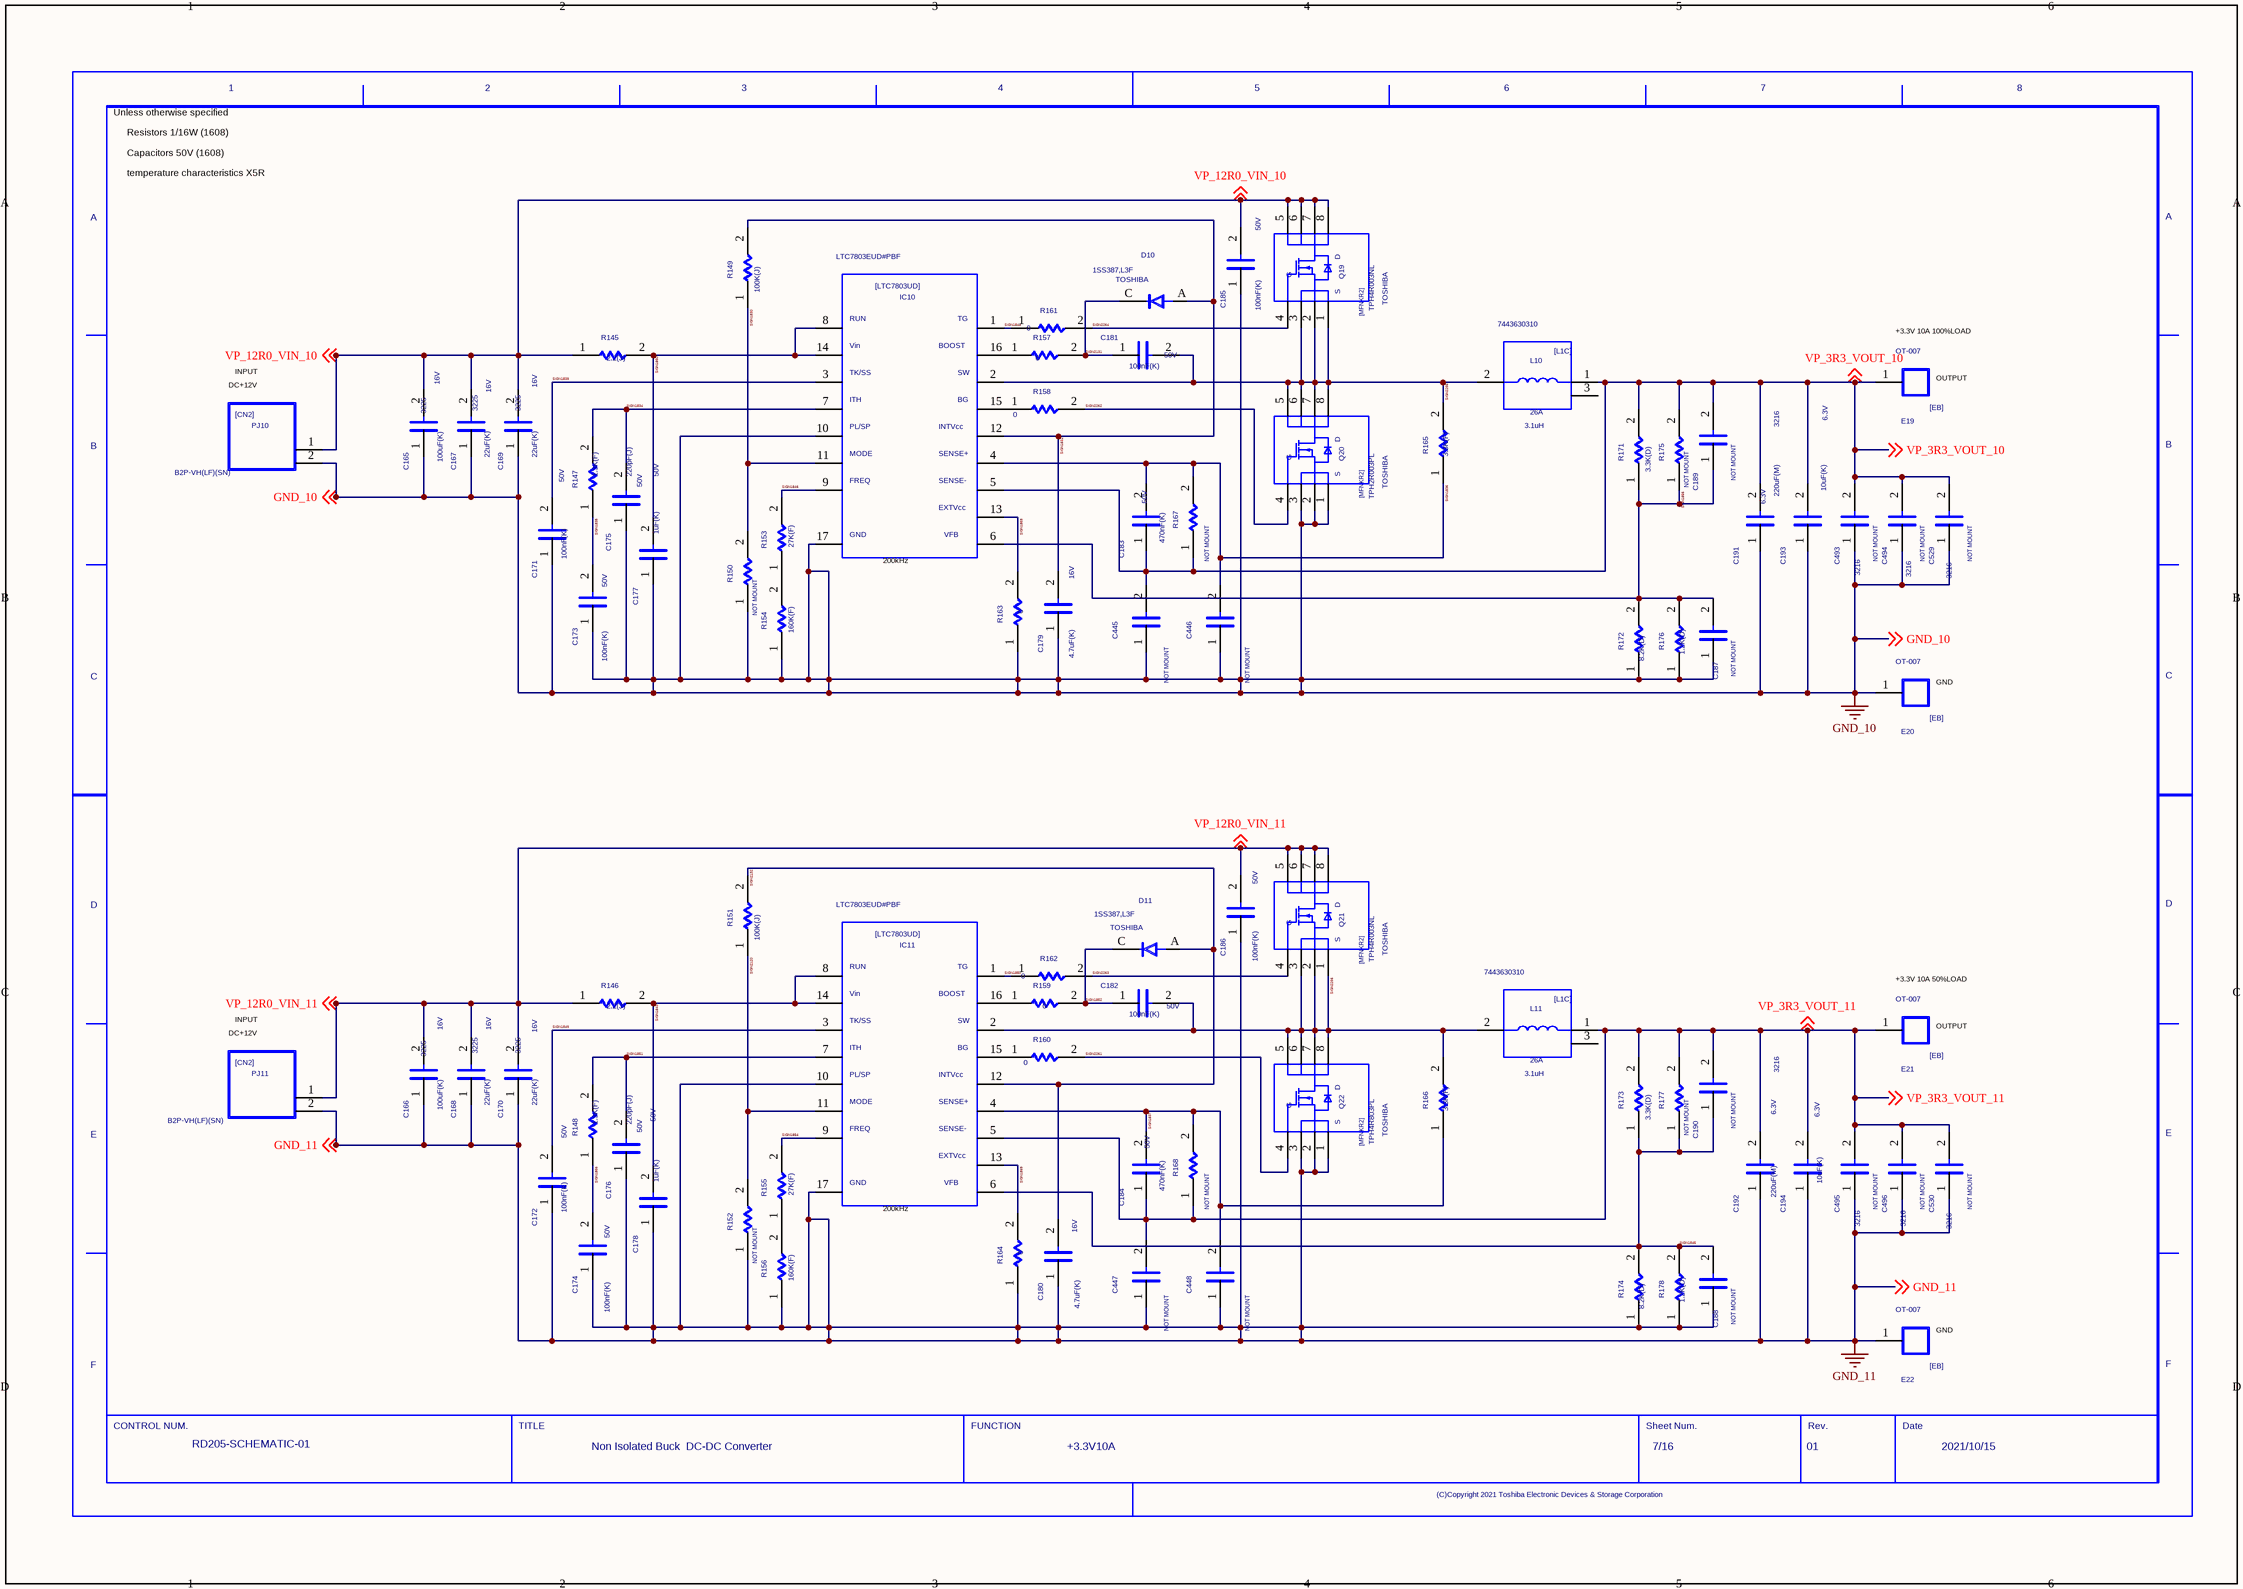
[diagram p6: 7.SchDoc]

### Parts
(Parts that share a designator on the sheet are numbered #1, #2 ... from top to bottom, then left to right.)
C165  SIZECODESMD: 3225  VAL2: 16V  VAL1: 100uF(K)  (hidden comment: C)
C166  SIZECODESMD: 3225  VAL2: 16V  VAL1: 100uF(K)  (hidden comment: C)
C167  SIZECODESMD: 3225  VAL2: 16V  VAL1: 22uF(K)  (hidden comment: C)
C168  SIZECODESMD: 3225  VAL2: 16V  VAL1: 22uF(K)  (hidden comment: C)
C169  SIZECODESMD: 3225  VAL2: 16V  VAL1: 22uF(K)  (hidden comment: C)
C170  SIZECODESMD: 3225  VAL2: 16V  VAL1: 22uF(K)  (hidden comment: C)
C171  VAL2: 50V  VAL1: 100nF(K)  (hidden comment: C)
C172  VAL2: 50V  VAL1: 100nF(K)  (hidden comment: C)
C173  VAL2: 50V  VAL1: 100nF(K)  (hidden comment: C)
C174  VAL2: 50V  VAL1: 100nF(K)  (hidden comment: C)
C175  VAL2: 50V  VAL1: 220pF(J)  (hidden comment: C)
C176  VAL2: 50V  VAL1: 220pF(J)  (hidden comment: C)
C177  VAL2: 50V  VAL1: 1uF(K)  (hidden comment: C)
C178  VAL2: 50V  VAL1: 1uF(K)  (hidden comment: C)
C179  VAL2: 16V  VAL1: 4.7uF(K)  (hidden comment: C)
C180  VAL2: 16V  VAL1: 4.7uF(K)  (hidden comment: C)
C181  VAL2: 50V  VAL1: 100nF(K)  (hidden comment: C)
C182  VAL2: 50V  VAL1: 100nF(K)  (hidden comment: C)
C183  VAL2: 50V  VAL1: 470nF(K)  (hidden comment: C)
C184  VAL2: 50V  VAL1: 470nF(K)  (hidden comment: C)
C185  VAL2: 50V  VAL1: 100nF(K)  (hidden comment: C)
C186  VAL2: 50V  VAL1: 100nF(K)  (hidden comment: C)
C187  NOTMOUNT: NOT MOUNT  (hidden comment: C)
C188  NOTMOUNT: NOT MOUNT  (hidden comment: C)
C189  NOTMOUNT: NOT MOUNT  (hidden comment: C)
C190  NOTMOUNT: NOT MOUNT  (hidden comment: C)
C191  SIZECODESMD: 3216  VAL2: 6.3V  VAL1: 220uF(M)  (hidden comment: C)
C192  SIZECODESMD: 3216  VAL2: 6.3V  VAL1: 220uF(M)  (hidden comment: C)
C193  VAL2: 6.3V  VAL1: 10uF(K)  (hidden comment: C)
C194  VAL2: 6.3V  VAL1: 10uF(K)  (hidden comment: C)
C445  NOTMOUNT: NOT MOUNT  (hidden comment: C)
C446  NOTMOUNT: NOT MOUNT  (hidden comment: C)
C447  NOTMOUNT: NOT MOUNT  (hidden comment: C)
C448  NOTMOUNT: NOT MOUNT  (hidden comment: C)
C493  NOTMOUNT: NOT MOUNT  SIZECODESMD: 3216  (hidden comment: C)
C494  NOTMOUNT: NOT MOUNT  SIZECODESMD: 3216  (hidden comment: C)
C495  NOTMOUNT: NOT MOUNT  SIZECODESMD: 3216  (hidden comment: C)
C496  NOTMOUNT: NOT MOUNT  SIZECODESMD: 3216  (hidden comment: C)
C529  NOTMOUNT: NOT MOUNT  SIZECODESMD: 3216  (hidden comment: C)
C530  NOTMOUNT: NOT MOUNT  SIZECODESMD: 3216  (hidden comment: C)
D10  USERCOMPTEXT3: TOSHIBA  VAL3: 1SS387,L3F  (hidden comment: D)
D11  USERCOMPTEXT3: TOSHIBA  VAL3: 1SS387,L3F  (hidden comment: D)
E19  VAL3: OT-007  (hidden comment: EB)
E20  VAL3: OT-007  (hidden comment: EB)
E21  VAL3: OT-007  (hidden comment: EB)
E22  VAL3: OT-007  (hidden comment: EB)
IC10  VAL3: LTC7803EUD#PBF  (hidden comment: LTC7803UD)
IC11  VAL3: LTC7803EUD#PBF  (hidden comment: LTC7803UD)
L10  VAL3: 7443630310  VAL2: 26A  VAL1: 3.1uH  (hidden comment: L1C)
L11  VAL3: 7443630310  VAL2: 26A  VAL1: 3.1uH  (hidden comment: L1C)
PJ10  VAL3: B2P-VH(LF)(SN)  (hidden comment: CN2)
PJ11  VAL3: B2P-VH(LF)(SN)  (hidden comment: CN2)
Q19  USERCOMPTEXT3: TOSHIBA  VAL3: TPH4R003NL  (hidden comment: MFNKR2)
Q20  USERCOMPTEXT3: TOSHIBA  VAL3: TPH2R003PL  (hidden comment: MFNKR2)
Q21  USERCOMPTEXT3: TOSHIBA  VAL3: TPH4R003NL  (hidden comment: MFNKR2)
Q22  USERCOMPTEXT3: TOSHIBA  VAL3: TPH4R803PL  (hidden comment: MFNKR2)
R145  VAL1: 2.2(J)  (hidden comment: R)
R146  VAL1: 2.2(J)  (hidden comment: R)
R147  VAL1: 1.3K(F)  (hidden comment: R)
R148  VAL1: 1.3K(F)  (hidden comment: R)
R149  VAL1: 100K(J)  (hidden comment: R)
R150  NOTMOUNT: NOT MOUNT  (hidden comment: R)
R151  VAL1: 100K(J)  (hidden comment: R)
R152  NOTMOUNT: NOT MOUNT  (hidden comment: R)
R153  VAL1: 27K(F)  (hidden comment: R)
R154  VAL1: 160K(F)  (hidden comment: R)
R155  VAL1: 27K(F)  (hidden comment: R)
R156  VAL1: 160K(F)  (hidden comment: R)
R157  VAL1: 0  (hidden comment: R)
R158  VAL1: 0  (hidden comment: R)
R159  VAL1: 0  (hidden comment: R)
R160  VAL1: 0  (hidden comment: R)
R161  VAL1: 0  (hidden comment: R)
R162  VAL1: 0  (hidden comment: R)
R163  VAL1: 0  (hidden comment: R)
R164  VAL1: 0  (hidden comment: R)
R165  VAL1: 3.3K(F)  (hidden comment: R)
R166  VAL1: 3.3K(F)  (hidden comment: R)
R167  NOTMOUNT: NOT MOUNT  (hidden comment: R)
R168  NOTMOUNT: NOT MOUNT  (hidden comment: R)
R171  VAL1: 3.3K(D)  (hidden comment: R)
R172  VAL1: 8.2K(D)  (hidden comment: R)
R173  VAL1: 3.3K(D)  (hidden comment: R)
R174  VAL1: 8.2K(D)  (hidden comment: R)
R175  NOTMOUNT: NOT MOUNT  (hidden comment: R)
R176  VAL1: 1.2K(D)  (hidden comment: R)
R177  NOTMOUNT: NOT MOUNT  (hidden comment: R)
R178  VAL1: 1.2K(D)  (hidden comment: R)
U?#7  DATE: 2021/10/15  SHEETNUMBER: 7/16  TITLE: Non Isolated Buck / DC-DC Converter  REVISION: 01  DRAWINGNUMBER: RD205-SCHEMATIC-01  FUNCTION: +3.3V10A  (hidden comment: WAKU_DEF100)

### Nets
GND_10: C165.1 C167.1 C169.1 C171.1 C173.1 C175.1 C177.1 C179.1 C185.1 C187.1 C191.1 C193.1 C445.1 C446.1 C493.1 C494.1 C529.1 E20.1 IC10.10 IC10.17 PJ10.2 Q20.1 Q20.2 Q20.3 R150.1 R154.1 R163.1 R172.1 R176.1 ; off-sheet GND_10
GND_11: C166.1 C168.1 C170.1 C172.1 C174.1 C176.1 C178.1 C180.1 C186.1 C188.1 C192.1 C194.1 C447.1 C448.1 C495.1 C496.1 C530.1 E22.1 IC11.10 IC11.17 PJ11.2 Q22.1 Q22.2 Q22.3 R152.1 R156.1 R164.1 R174.1 R178.1 ; off-sheet GND_11
SIGN1830: IC10.11 R149.1 R150.2
SIGN1831: C179.2 D10.A IC10.12 R149.2
SIGN1834: C175.2 IC10.7 R147.2
SIGN1835: C173.2 R147.1
SIGN1836: C183.2 C446.2 IC10.4 R165.1 R167.2
SIGN1837: C184.2 C448.2 IC11.4 R166.1 R168.2
SIGN1839: C171.2 IC10.3
SIGN1843: C178.2 IC11.8 IC11.14 R146.2
SIGN1845: C188.2 C190.1 IC11.6 R173.1 R174.2 R177.1 R178.2
SIGN1846: IC10.9 R153.2
SIGN1848: IC10.1 R161.1
SIGN1849: C172.2 IC11.3
SIGN1850: IC11.1 R162.1
SIGN1851: C176.2 IC11.7 R148.2
SIGN1852: C182.1 D11.C R159.2
SIGN1854: IC11.9 R155.2
SIGN1856: C187.2 C189.1 IC10.6 R171.1 R172.2 R175.1 R176.2
SIGN1860: C177.2 IC10.8 IC10.14 R145.2
SIGN1866: C174.2 R148.1
SIGN1868: IC10.13 R163.2
SIGN1869: IC11.13 R164.2
SIGN2120: IC11.11 R151.1 R152.2
SIGN2131: C181.1 D10.C R157.2
SIGN2132: C180.2 D11.A IC11.12 R151.2
SIGN2261: Q22.4 R160.2
SIGN2262: Q20.4 R158.2
SIGN2263: Q21.4 R162.2
SIGN2264: Q19.4 R161.2
SIGN2265: C181.2 IC10.2 L10.2 Q19.1 Q19.2 Q19.3 Q20.5 Q20.6 Q20.7 Q20.8 R165.2
SIGN2266: C182.2 IC11.2 L11.2 Q21.1 Q21.2 Q21.3 Q22.5 Q22.6 Q22.7 Q22.8 R166.2
VP_3R3_VOUT_10: C183.1 C189.2 C191.2 C193.2 C445.2 C493.2 C494.2 C529.2 E19.1 IC10.5 L10.1 R167.1 R171.2 R175.2 ; off-sheet VP_3R3_VOUT_10
VP_3R3_VOUT_11: C184.1 C190.2 C192.2 C194.2 C447.2 C495.2 C496.2 C530.2 E21.1 IC11.5 L11.1 R168.1 R173.2 R177.2 ; off-sheet VP_3R3_VOUT_11
VP_12R0_VIN_10: C165.2 C167.2 C169.2 C185.2 PJ10.1 Q19.5 Q19.6 Q19.7 Q19.8 R145.1 ; off-sheet VP_12R0_VIN_10
VP_12R0_VIN_11: C166.2 C168.2 C170.2 C186.2 PJ11.1 Q21.5 Q21.6 Q21.7 Q21.8 R146.1 ; off-sheet VP_12R0_VIN_11
NetIC10_15: IC10.15 R158.1
NetIC10_16: IC10.16 R157.1
NetIC11_15: IC11.15 R160.1
NetIC11_16: IC11.16 R159.1
NetR153_1: R153.1 R154.2
NetR155_1: R155.1 R156.2

Not connected (* = marked no-connect by the designer): L10 3; L11 3

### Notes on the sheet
- Unless otherwise specified
- Resistors 1/16W (1608)
- Capacitors 50V (1608)
- temperature characteristics X5R
- DC+12V
- INPUT
- (near E19) +3.3V 10A 100%LOAD
- (near E19) OUTPUT
- (near IC10) 200kHz
- (near E20) GND
- (near E21) +3.3V 10A 50%LOAD
- (near E21) OUTPUT
- (near IC11) 200kHz
- (near E22) GND

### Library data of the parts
C165 C166 = C_Dup1: SQ_PART_MODEL: CON_100n; FNPARTSNAMEG: CHIP CERAMIC CAPACITOR (3225); USEINPARTSLIST: YES; OriginalSymbolOrigin: (2540,7620); MFSOLDERINGPROP: .; TEMPCHARACTERI2: B; MFFORMINGDIVP: KC; OUMECLASSIFICATION: セラミックコンデンサ; MFMOUNTSYMBOLP: 90; CDMASTERCADCELG: DC903A; PCODE: P03276001115; FNCLASSCODEG: P03-03; MAXGCOUNT: 1; RATEDVOLTAGE: 250; COMPONENTNAME: G36030160049; OUMEMAKER: KYC 京セラ; MFPACKAGEMETHOP: S; NOMINALCAPACITA: 100n; OUMEMAKERKATAMEI: CF32W5R104K250AT; CAPACITANCETOLE: K
C167-C170 = C_Dup1: SQ_PART_MODEL: CON_22u; FNPARTSNAMEG: CHIP CERAMIC CAPACITOR (3225); USEINPARTSLIST: YES; OriginalSymbolOrigin: (2540,7620); MFSOLDERINGPROP: .; TEMPCHARACTERI2: B; MFFORMINGDIVP: KC; OUMECLASSIFICATION: セラミックコンデンサ; MFMOUNTSYMBOLP: 80; CDMASTERCADCELG: DC903A; PCODE: P03043035626; FNCLASSCODEG: P03-03; MAXGCOUNT: 1; RATEDVOLTAGE: 6.3; COMPONENTNAME: G36030119054; OUMEMAKER: TYD 太陽誘電; MFPACKAGEMETHOP: S; NOMINALCAPACITA: 22u; OUMEMAKERKATAMEI: JMK325BJ226KM-T; CAPACITANCETOLE: K
C171-C174 C181 C182 C185 C186 = C_Dup1: SQ_PART_MODEL: CON_100n; FNPARTSNAMEG: CHIP CERAMIC CAPACITOR (1608); USEINPARTSLIST: YES; OriginalSymbolOrigin: (2540,7620); MFSOLDERINGPROP: .; TEMPCHARACTERI2: B; MFFORMINGDIVP: KC; OUMECLASSIFICATION: セラミックコンデンサ; SIZECODESMD: 1608; MFMOUNTSYMBOLP: 80; CDMASTERCADCELG: C8100E; PCODE: P03B000000E4; FNCLASSCODEG: P03-03; MAXGCOUNT: 1; RATEDVOLTAGE: 16; COMPONENTNAME: GDM030000598; OUMEMAKER: MRT 村田製作所; MFPACKAGEMETHOP: S; NOMINALCAPACITA: 100n; OUMEMAKERKATAMEI: GRM188B11C104KA01C; CAPACITANCETOLE: K
C175 C176 = C_Dup1: SQ_PART_MODEL: CON_220p; FNPARTSNAMEG: CHIP CERAMIC CAPACITOR (1608); USEINPARTSLIST: YES; OriginalSymbolOrigin: (2540,7620); CDMASTERCADCELG: C8100E; MFSOLDERINGPROP: .; TEMPCHARACTERI2: CH; MFFORMINGDIVP: KC; OUMECLASSIFICATION: セラミックコンデンサ; SIZECODESMD: 1608; MFMOUNTSYMBOLP: 80; PCODE: P03039269127; FNCLASSCODEG: P03-03; MAXGCOUNT: 1; RATEDVOLTAGE: 50; COMPONENTNAME: G36030011488; OUMEMAKER: KYC 京セラ; MFPACKAGEMETHOP: S; NOMINALCAPACITA: 220p; OUMEMAKERKATAMEI: CM105CH221J50AT; CAPACITANCETOLE: J
C177 C178 = C_Dup1: SQ_PART_MODEL: CON_1u; FNPARTSNAMEG: CHIP CERAMIC CAPACITOR (1608); USEINPARTSLIST: YES; OriginalSymbolOrigin: (2540,7620); MFSOLDERINGPROP: .; TEMPCHARACTERI2: B; MFFORMINGDIVP: KC; OUMECLASSIFICATION: セラミックコンデンサ; SIZECODESMD: 1608; MFMOUNTSYMBOLP: 80; CDMASTERCADCELG: C8100E; PCODE: P03039ACE122; FNCLASSCODEG: P03-03; MAXGCOUNT: 1; RATEDVOLTAGE: 6.3; COMPONENTNAME: G36030104159; OUMEMAKER: KYC 京セラ; MFPACKAGEMETHOP: S; NOMINALCAPACITA: 1u; OUMEMAKERKATAMEI: CM105B105K06ATN; CAPACITANCETOLE: K
C179 C180 = C_Dup1: SQ_PART_MODEL: CON_4.7u; FNPARTSNAMEG: CHIP CERAMIC CAPACITOR (1608); USEINPARTSLIST: YES; OriginalSymbolOrigin: (2540,7620); MFSOLDERINGPROP: .; TEMPCHARACTERI2: B; MFFORMINGDIVP: KC; OUMECLASSIFICATION: セラミックコンデンサ; SIZECODESMD: 1608; MFMOUNTSYMBOLP: 80; CDMASTERCADCELG: C8100E; PCODE: P03B000000MS; FNCLASSCODEG: P03-03; MAXGCOUNT: 1; RATEDVOLTAGE: 4; COMPONENTNAME: GDM030000053; OUMEMAKER: KYC 京セラ; MFPACKAGEMETHOP: S; NOMINALCAPACITA: 4.7u; OUMEMAKERKATAMEI: CM105B475M04AT; CAPACITANCETOLE: M
C183 C184 = C_Dup1: SQ_PART_MODEL: CON_470n; FNPARTSNAMEG: CHIP CERAMIC CAPACITOR (1608); USEINPARTSLIST: YES; OriginalSymbolOrigin: (2540,7620); MFSOLDERINGPROP: .; TEMPCHARACTERI2: B; MFFORMINGDIVP: KC; OUMECLASSIFICATION: セラミックコンデンサ; SIZECODESMD: 1608; MFMOUNTSYMBOLP: 80; CDMASTERCADCELG: C8100E; PCODE: P03039ABG127; FNCLASSCODEG: P03-03; MAXGCOUNT: 1; RATEDVOLTAGE: 10; COMPONENTNAME: GDM030001129; OUMEMAKER: KYC 京セラ; MFPACKAGEMETHOP: S; NOMINALCAPACITA: 470n; OUMEMAKERKATAMEI: CM105B474K10AT; CAPACITANCETOLE: K
C187-C190 = C_Dup1: SQ_PART_MODEL: CON_100p; FNPARTSNAMEG: CHIP CERAMIC CAPACITOR (1608); USEINPARTSLIST: YES; OriginalSymbolOrigin: (2540,7620); TOLERANCE: J; ASIMVALUE: 100P; MFSOLDERINGPROP: .; TEMPCHARACTERI2: CH; MFFORMINGDIVP: KC; OUMECLASSIFICATION: セラミックコンデンサ; SIZECODESMD: 1608; MFMOUNTSYMBOLP: 80; CDMASTERCADCELG: C8100E; PCODE: P03039177125; FNCLASSCODEG: P03-03; MAXGCOUNT: 1; RATEDVOLTAGE: 50; COMPONENTNAME: G36030011365; OUMEMAKER: KYC 京セラ; MFPACKAGEMETHOP: S; OUMEMAKERKATAMEI: CM105CH101J50AT; VAL2: 50V; VAL1: 100pF(J)
C191 C192 = C_Dup1: SQ_PART_MODEL: CON_22u; FNPARTSNAMEG: CHIP CERAMIC CAPACITOR (3216); USEINPARTSLIST: YES; OriginalSymbolOrigin: (2540,7620); MFSOLDERINGPROP: .; TEMPCHARACTERI2: B; MFFORMINGDIVP: KC; OUMECLASSIFICATION: セラミックコンデンサ; MFMOUNTSYMBOLP: 80; CDMASTERCADCELG: DC901A; PCODE: P03B0000004V; FNCLASSCODEG: P03-03; MAXGCOUNT: 1; RATEDVOLTAGE: 6.3; COMPONENTNAME: GDM030000020; OUMEMAKER: KYC 京セラ; MFPACKAGEMETHOP: S; NOMINALCAPACITA: 22u; OUMEMAKERKATAMEI: CM316B226M06AT; CAPACITANCETOLE: M
C193 C194 = C_Dup1: SQ_PART_MODEL: CON_1u; FNPARTSNAMEG: CHIP CERAMIC CAPACITOR (1608); PARTCOMMENT: 代表セル<KC0008> がフットプリントに登録されていません。; USEINPARTSLIST: YES; OriginalSymbolOrigin: (2540,7620); MFSOLDERINGPROP: .; TEMPCHARACTERI2: B; MFFORMINGDIVP: KC; OUMECLASSIFICATION: セラミックコンデンサ; SIZECODESMD: 1608; MFMOUNTSYMBOLP: 80; CDMASTERCADCELG: KC0008; PCODE: P03B000000ZQ; FNCLASSCODEG: P03-03; MAXGCOUNT: 1; RATEDVOLTAGE: 6.3; COMPONENTNAME: GDM030000202; OUMEMAKER: MRT 村田製作所; MFPACKAGEMETHOP: S; NOMINALCAPACITA: 1u; OUMEMAKERKATAMEI: GRM185B10J105KE21D; CAPACITANCETOLE: K
C445-C448 = C_Dup1: SQ_PART_MODEL: CON_220n; FNPARTSNAMEG: CHIP CERAMIC CAPACITOR (1608); PARTCOMMENT: 代表セル<KC0008> がフットプリントに登録されていません。; USEINPARTSLIST: YES; OriginalSymbolOrigin: (2540,7620); MFSOLDERINGPROP: .; TEMPCHARACTERI2: B; MFFORMINGDIVP: KC; OUMECLASSIFICATION: セラミックコンデンサ; SIZECODESMD: 1608; MFMOUNTSYMBOLP: 80; CDMASTERCADCELG: KC0008; PCODE: P03B000001L3; FNCLASSCODEG: P03-03; MAXGCOUNT: 1; RATEDVOLTAGE: 16; COMPONENTNAME: GDM030001129; OUMEMAKER: MRT 村田製作所; MFPACKAGEMETHOP: S; NOMINALCAPACITA: 220n; OUMEMAKERKATAMEI: GRM188B11C224KA01D; VAL2: 16V; VAL1: 220nF(K); CAPACITANCETOLE: K
C493-C496 C529 C530 = C_Dup1: SQ_PART_MODEL: CON_22u; FNPARTSNAMEG: CHIP CERAMIC CAPACITOR (3216); USEINPARTSLIST: YES; OriginalSymbolOrigin: (2540,7620); MFSOLDERINGPROP: .; TEMPCHARACTERI2: B; MFFORMINGDIVP: KC; OUMECLASSIFICATION: セラミックコンデンサ; MFMOUNTSYMBOLP: 80; CDMASTERCADCELG: DC901A; PCODE: P03B0000004V; FNCLASSCODEG: P03-03; MAXGCOUNT: 1; RATEDVOLTAGE: 6.3; COMPONENTNAME: GDM030000020; OUMEMAKER: KYC 京セラ; MFPACKAGEMETHOP: S; NOMINALCAPACITA: 22u; OUMEMAKERKATAMEI: CM316B226M06AT; VAL2: 6.3V; VAL1: 22uF(M); CAPACITANCETOLE: M
D10 D11 = D_Dup1: FNPARTSNAMEG: DIODE; USEINPARTSLIST: YES; PARTNAME: GDM420000143; SAVEAREA0: -565,-171,12979,8058; SAVECOUNT: 1; OriginalSymbolOrigin: (2540,5080); FORWARDVOLTAGEM: 0; MAXREVERSEVOLTA: 80; COMPONENTNAME: GDM420000143_package; MFSOLDERINGPROP: .; OUMEMAKER: TSB 東芝（ＹＰＳＳ）; QUADMODEL: dummymodel; MFPACKAGEMETHOP: S; MFFORMINGDIVP: MM; MOUNTINGFORMSMD: SMD; OUMECLASSIFICATION: 小信号ダイオード; OUMEMAKERKATAMEI: 1SS387(TPH3,F); CDMASTERCADCELG: D8101D; PCODE: P42B0000008E; FNCLASSCODEG: P42-01
E19-E22 = EB_Dup1: FNPARTSNAMEG: TERMINAL; USEINPARTSLIST: YES; PARTNAME: 5P9L1232P001; OUMEPARTTYPE: TB; OriginalSymbolOrigin: (2540,12700); COMPONENTNAME: 5P9L1232P001_package; MAXGCOUNT: 1; MFSOLDERINGPROP: .; OUMEMAKER: オサダ; QUADMODEL: dummymodel; MFPACKAGEMETHOP: I; MFFORMINGDIVP: OD; OUMECLASSIFICATION: 端子台、端子板; CDMASTERCADCELG: DE0009; KIND: PBS; PCODE: P29045001117; TERMINALSTYLE: SC; FNCLASSCODEG: P29-01
IC10 IC11 = LTC7803UD: as IC7 on sheet 5
L10 L11 = L1C_Dup1: USEINPARTSLIST: YES; PARTNAME: 7443630140; SAVECOUNT: 6; SAVEAREA0: -5636,-341,27978,18652; OriginalSymbolOrigin: (5080,15240); COMPONENTNAME: L1C_L1C; MAXGCOUNT: 1; OUMEMAKER: WURTH
PJ10 PJ11 = CN2_Dup1: FNPARTSNAMEG: 3.96PITCH NYLON CONNECTOR; USEINPARTSLIST: YES; PARTNAME: G36220114012; OUMEPARTTYPE: CN; OriginalSymbolOrigin: (2540,15240); MAXGCOUNT: 1; RATEDCURRENT: 7; COMPONENTNAME: G36220114012_package; MFSOLDERINGPROP: .; OUMEMAKER: JST 日本圧着端子製造; NUMBEROFCONTACT: 2; QUADMODEL: dummymodel; MFPACKAGEMETHOP: I; MFFORMINGDIVP: CU; CONTACTPITCH: 3.96m; OUMEMAKERKATAMEI: B2P-VH; CDMASTERCADCELG: DPJ514; PCODE: P22346001114; TERMINALSTYLE: PW; FNCLASSCODEG: P22-10
Q19-Q22 = MFNKR2: as Q13-Q16 on sheet 5
R145 R146 = R_Dup1: SQ_PART_MODEL: RES_2.2; FNPARTSNAMEG: CHIP RESISTOR (1608); USEINPARTSLIST: YES; OriginalSymbolOrigin: (5080,5080); TOLERANCE: J; ASIMVALUE: 2.2; MAXGCOUNT: 1; COMPONENTNAME: G36010011507; MFSOLDERINGPROP: .; OUMEMAKER: NAE 松下電子部品; MFPACKAGEMETHOP: S; MFFORMINGDIVP: KC; MOUNTINGFORMSMD: SMD; OUMECLASSIFICATION: 表面実装用固定抵抗器; MFMOUNTSYMBOLP: 80; POWERRATING: 63m; OUMEMAKERKATAMEI: ERJ3GEYJ2R2V; NUMBEROFELEMENT: 0; VAL2: 62.5mW; CDMASTERCADCELG: DR802R; PCODE: P01042157622; FNCLASSCODEG: P01-08
R147 R148 = R_Dup1: SQ_PART_MODEL: RES_1.3K; FNPARTSNAMEG: CHIP RESISTOR (1608); USEINPARTSLIST: YES; OriginalSymbolOrigin: (5080,5080); TOLERANCE: F; ASIMVALUE: 1.3K; MAXGCOUNT: 1; COMPONENTNAME: G36010104049; MFSOLDERINGPROP: .; OUMEMAKER: HDK 北陸電気工業; MFPACKAGEMETHOP: S; MFFORMINGDIVP: KC; MOUNTINGFORMSMD: SMD; OUMECLASSIFICATION: 表面実装用固定抵抗器; MFMOUNTSYMBOLP: 80; POWERRATING: 63m; OUMEMAKERKATAMEI: CR1/16 132FV; NUMBEROFELEMENT: 0; VAL2: 62.5mW; CDMASTERCADCELG: DR802R; PCODE: P01042017223; FNCLASSCODEG: P01-08
R149 R151 = R_Dup1: SQ_PART_MODEL: RES_100K; FNPARTSNAMEG: CHIP RESISTOR (1608); USEINPARTSLIST: YES; OriginalSymbolOrigin: (5080,5080); TOLERANCE: J; ASIMVALUE: 100K; MFSOLDERINGPROP: .; MFPACKAGEMETHOP: S; MFFORMINGDIVP: KC; MOUNTINGFORMSMD: SMD; MFMOUNTSYMBOLP: 80; NUMBEROFELEMENT: 0; PCODE: P01042047220; MAXGCOUNT: 1; COMPONENTNAME: G36010011057; OUMEMAKER: HDK 北陸電気工業; OUMECLASSIFICATION: 表面実装用固定抵抗器; POWERRATING: 63m; OUMEMAKERKATAMEI: CR1/16 104JV; VAL2: 62.5mW; CDMASTERCADCELG: DR802R; FNCLASSCODEG: P01-08
R150 R152 = R_Dup1: SQ_PART_MODEL: RES_10; FNPARTSNAMEG: CHIP RESISTOR (1608); USEINPARTSLIST: YES; OriginalSymbolOrigin: (5080,5080); TOLERANCE: F; ASIMVALUE: 10; MFSOLDERINGPROP: .; MFPACKAGEMETHOP: S; MFFORMINGDIVP: KC; MOUNTINGFORMSMD: SMD; MFMOUNTSYMBOLP: 80; NUMBEROFELEMENT: 0; PCODE: P01042036620; MAXGCOUNT: 1; COMPONENTNAME: G36010104063; OUMEMAKER: NAE 松下電子部品; OUMECLASSIFICATION: 表面実装用固定抵抗器; POWERRATING: 63m; OUMEMAKERKATAMEI: ERJ3GEYF100V; VAL2: 62.5mW; VAL1: 10(F); CDMASTERCADCELG: DR802R; FNCLASSCODEG: P01-08
R153 R155 = R_Dup1: SQ_PART_MODEL: RES_27K; FNPARTSNAMEG: CHIP RESISTOR (1608); USEINPARTSLIST: YES; OriginalSymbolOrigin: (5080,5080); MAXGCOUNT: 1; TOLERANCE: F; COMPONENTNAME: G36010027195; MFSOLDERINGPROP: .; OUMEMAKER: NAE 松下電子部品; MFPACKAGEMETHOP: S; MFFORMINGDIVP: KC; MOUNTINGFORMSMD: SMD; OUMECLASSIFICATION: 表面実装用固定抵抗器; ASIMVALUE: 27K; MFMOUNTSYMBOLP: 80; POWERRATING: 63m; OUMEMAKERKATAMEI: ERJ3GEYF273V; NUMBEROFELEMENT: 0; VAL2: 62.5mW; CDMASTERCADCELG: DR802R; PCODE: P01042508622; FNCLASSCODEG: P01-08
R154 R156 = R_Dup1: SQ_PART_MODEL: RES_160K; FNPARTSNAMEG: CHIP RESISTOR (1608); USEINPARTSLIST: YES; OriginalSymbolOrigin: (5080,5080); MAXGCOUNT: 1; COMPONENTNAME: G51011061108; MFSOLDERINGPROP: .; OUMEMAKER: HDK 北陸電気工業; MFPACKAGEMETHOP: S; MFFORMINGDIVP: KC; MOUNTINGFORMSMD: SMD; OUMECLASSIFICATION: 表面実装用固定抵抗器; RESISTANCETOLER: F; MFMOUNTSYMBOLP: 80; POWERRATING: 63m; OUMEMAKERKATAMEI: CR1/16 164FV; NOMINALRESISTAN: 160K; NUMBEROFELEMENT: 0; VAL2: 62.5mW; CDMASTERCADCELG: DR802R; PCODE: P01042125225; FNCLASSCODEG: P01-08
R157 R159 R163 R164 = R_Dup1: SQ_PART_MODEL: RES_10; FNPARTSNAMEG: CHIP RESISTOR (1608); USEINPARTSLIST: YES; OriginalSymbolOrigin: (5080,5080); TOLERANCE: F; ASIMVALUE: 10; MFSOLDERINGPROP: .; MFPACKAGEMETHOP: S; MFFORMINGDIVP: KC; MOUNTINGFORMSMD: SMD; MFMOUNTSYMBOLP: 80; PCODE: P01042036620; MAXGCOUNT: 1; COMPONENTNAME: G36010104063; OUMEMAKER: NAE 松下電子部品; OUMECLASSIFICATION: 表面実装用固定抵抗器; POWERRATING: 63m; OUMEMAKERKATAMEI: ERJ3GEYF100V; VAL2: 62.5mW; CDMASTERCADCELG: DR802R; FNCLASSCODEG: P01-08
R158 R160-R162 = R_Dup1: SQ_PART_MODEL: RES_10; FNPARTSNAMEG: CHIP RESISTOR (2012); USEINPARTSLIST: YES; OriginalSymbolOrigin: (5080,5080); MAXGCOUNT: 1; TOLERANCE: F; COMPONENTNAME: 5P9L1083P100; MFSOLDERINGPROP: .; OUMEMAKER: 北陸電気工業; MFPACKAGEMETHOP: S; MFFORMINGDIVP: KC; MOUNTINGFORMSMD: SMD; OUMECLASSIFICATION: 表面実装用固定抵抗器; ASIMVALUE: 10; MFMOUNTSYMBOLP: 90; POWERRATING: 100m; OUMEMAKERKATAMEI: CR1/10 100FV Pb(F); VAL2: 125mW; CDMASTERCADCELG: DR910A; PCODE: P01043091222; FNCLASSCODEG: P01-08
R165 R166 = R_Dup1: SQ_PART_MODEL: RES_3.3K; FNPARTSNAMEG: CHIP RESISTOR (1608); USEINPARTSLIST: YES; OriginalSymbolOrigin: (5080,5080); TOLERANCE: F; ASIMVALUE: 3.3K; MAXGCOUNT: 1; COMPONENTNAME: G5101105R107; MFSOLDERINGPROP: .; OUMEMAKER: ROH ロー・; MFPACKAGEMETHOP: S; MFFORMINGDIVP: KC; MOUNTINGFORMSMD: SMD; OUMECLASSIFICATION: 表面実装用固定抵抗器; MFMOUNTSYMBOLP: 80; POWERRATING: 63m; OUMEMAKERKATAMEI: MCR03EZPFX3301; NUMBEROFELEMENT: 0; VAL2: 62.5mW; CDMASTERCADCELG: DR802R; PCODE: P01042250729; FNCLASSCODEG: P01-08
R167 R168 = R_Dup1: SQ_PART_MODEL: RES_68K; FNPARTSNAMEG: CHIP RESISTOR (1608); USEINPARTSLIST: YES; OriginalSymbolOrigin: (5080,5080); TOLERANCE: F; ASIMVALUE: 68K; MAXGCOUNT: 1; COMPONENTNAME: G36010027126; MFSOLDERINGPROP: .; OUMEMAKER: HDK 北陸電気工業; MFPACKAGEMETHOP: S; MFFORMINGDIVP: KC; MOUNTINGFORMSMD: SMD; OUMECLASSIFICATION: 表面実装用固定抵抗器; MFMOUNTSYMBOLP: 80; POWERRATING: 63m; OUMEMAKERKATAMEI: CR1/16 683FV; NUMBEROFELEMENT: 0; VAL2: 62.5mW; VAL1: 68K(F); CDMASTERCADCELG: DR802R; PCODE: P01042456220; FNCLASSCODEG: P01-08
R171 R173 = R_Dup1: SQ_PART_MODEL: RES_3.3K; FNPARTSNAMEG: CHIP RESISTOR (1608); USEINPARTSLIST: YES; OriginalSymbolOrigin: (5080,5080); MAXGCOUNT: 1; COMPONENTNAME: G36010014485; MFSOLDERINGPROP: .; OUMEMAKER: SSM 進工業; MFPACKAGEMETHOP: S; MFFORMINGDIVP: KC; MOUNTINGFORMSMD: SMD; OUMECLASSIFICATION: 表面実装用固定抵抗器; RESISTANCETOLER: D; MFMOUNTSYMBOLP: 80; POWERRATING: 63m; OUMEMAKERKATAMEI: RR0816P-332-D; NOMINALRESISTAN: 3.3K; NUMBEROFELEMENT: 0; VAL2: 62.5mW; CDMASTERCADCELG: DR802R; PCODE: P01042249822; FNCLASSCODEG: P01-08
R172 R174 = R_Dup1: ICX_PART_MODEL: RES_8.2K; FNPARTSNAMEG: CHIP RESISTOR (1608); OriginalSymbolOrigin: (5080,5080); FNCLASSCODEG: P01-08; PCODE: P01117051114; CDMASTERCADCELG: DR802R; USEWITHSCHEMA: YES; VAL2: 62.5mW; NUMBEROFELEMENT: 0; NOMINALRESISTAN: 8.2K; OUMEMAKERKATAMEI: RK73G1JTD822D; POWERRATING: 63m; MFMOUNTSYMBOLP: 80; RESISTANCETOLER: D; FUNCTION: G36010129479; OUMECLASSIFICATION: 表面実装用固定抵抗器; MOUNTINGFORMSMD: SMD; MFFORMINGDIVP: KC; MFPACKAGEMETHOP: S; OUMEMAKER: KOA ＫＯＡ; MFSOLDERINGPROP: .; MAXGCOUNT: 1
R175 R177 = R_Dup1: SQ_PART_MODEL: RES_3.3K; FNPARTSNAMEG: CHIP RESISTOR (1608); USEINPARTSLIST: YES; OriginalSymbolOrigin: (5080,5080); TOLERANCE: F; ASIMVALUE: 3.3K; MAXGCOUNT: 1; COMPONENTNAME: G36010027027; MFSOLDERINGPROP: .; OUMEMAKER: ROH ロー・; MFPACKAGEMETHOP: S; MFFORMINGDIVP: KC; MOUNTINGFORMSMD: SMD; OUMECLASSIFICATION: 表面実装用固定抵抗器; MFMOUNTSYMBOLP: 80; POWERRATING: 63m; OUMEMAKERKATAMEI: MCR03EZPFX3301; NUMBEROFELEMENT: 0; VAL2: 62.5mW; VAL1: 3.3K(F); CDMASTERCADCELG: DR802R; PCODE: P01042250729; FNCLASSCODEG: P01-08
R176 R178 = R_Dup1: ICX_PART_MODEL: RES_1.2K; FNPARTSNAMEG: CHIP RESISTOR (1608); OriginalSymbolOrigin: (5080,5080); FNCLASSCODEG: P01-08; PCODE: P01117031116; CDMASTERCADCELG: DR802R; USEWITHSCHEMA: YES; VAL2: 62.5mW; NUMBEROFELEMENT: 0; NOMINALRESISTAN: 1.2K; OUMEMAKERKATAMEI: RK73G1JTD122D; POWERRATING: 63m; MFMOUNTSYMBOLP: 80; RESISTANCETOLER: D; FUNCTION: G36010129271; OUMECLASSIFICATION: 表面実装用固定抵抗器; MOUNTINGFORMSMD: SMD; MFFORMINGDIVP: KC; MFPACKAGEMETHOP: S; OUMEMAKER: KOA ＫＯＡ; MFSOLDERINGPROP: .; MAXGCOUNT: 1
U?#7 = WAKU_DEF100: PLOTTIME: HH:MM; SAVEAREA0: 330961,54,387907,31546; TIME: 19:23:07; UPDATEUSER: t5459927; UPDATETIME: 15:27:13; SAVECOUNT: 6; OriginalSymbolOrigin: (10160,284480); DESIGNED: ***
